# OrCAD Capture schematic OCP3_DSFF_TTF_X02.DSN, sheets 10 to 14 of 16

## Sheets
10 PAGE11 - NCSI Isolation: size Custom
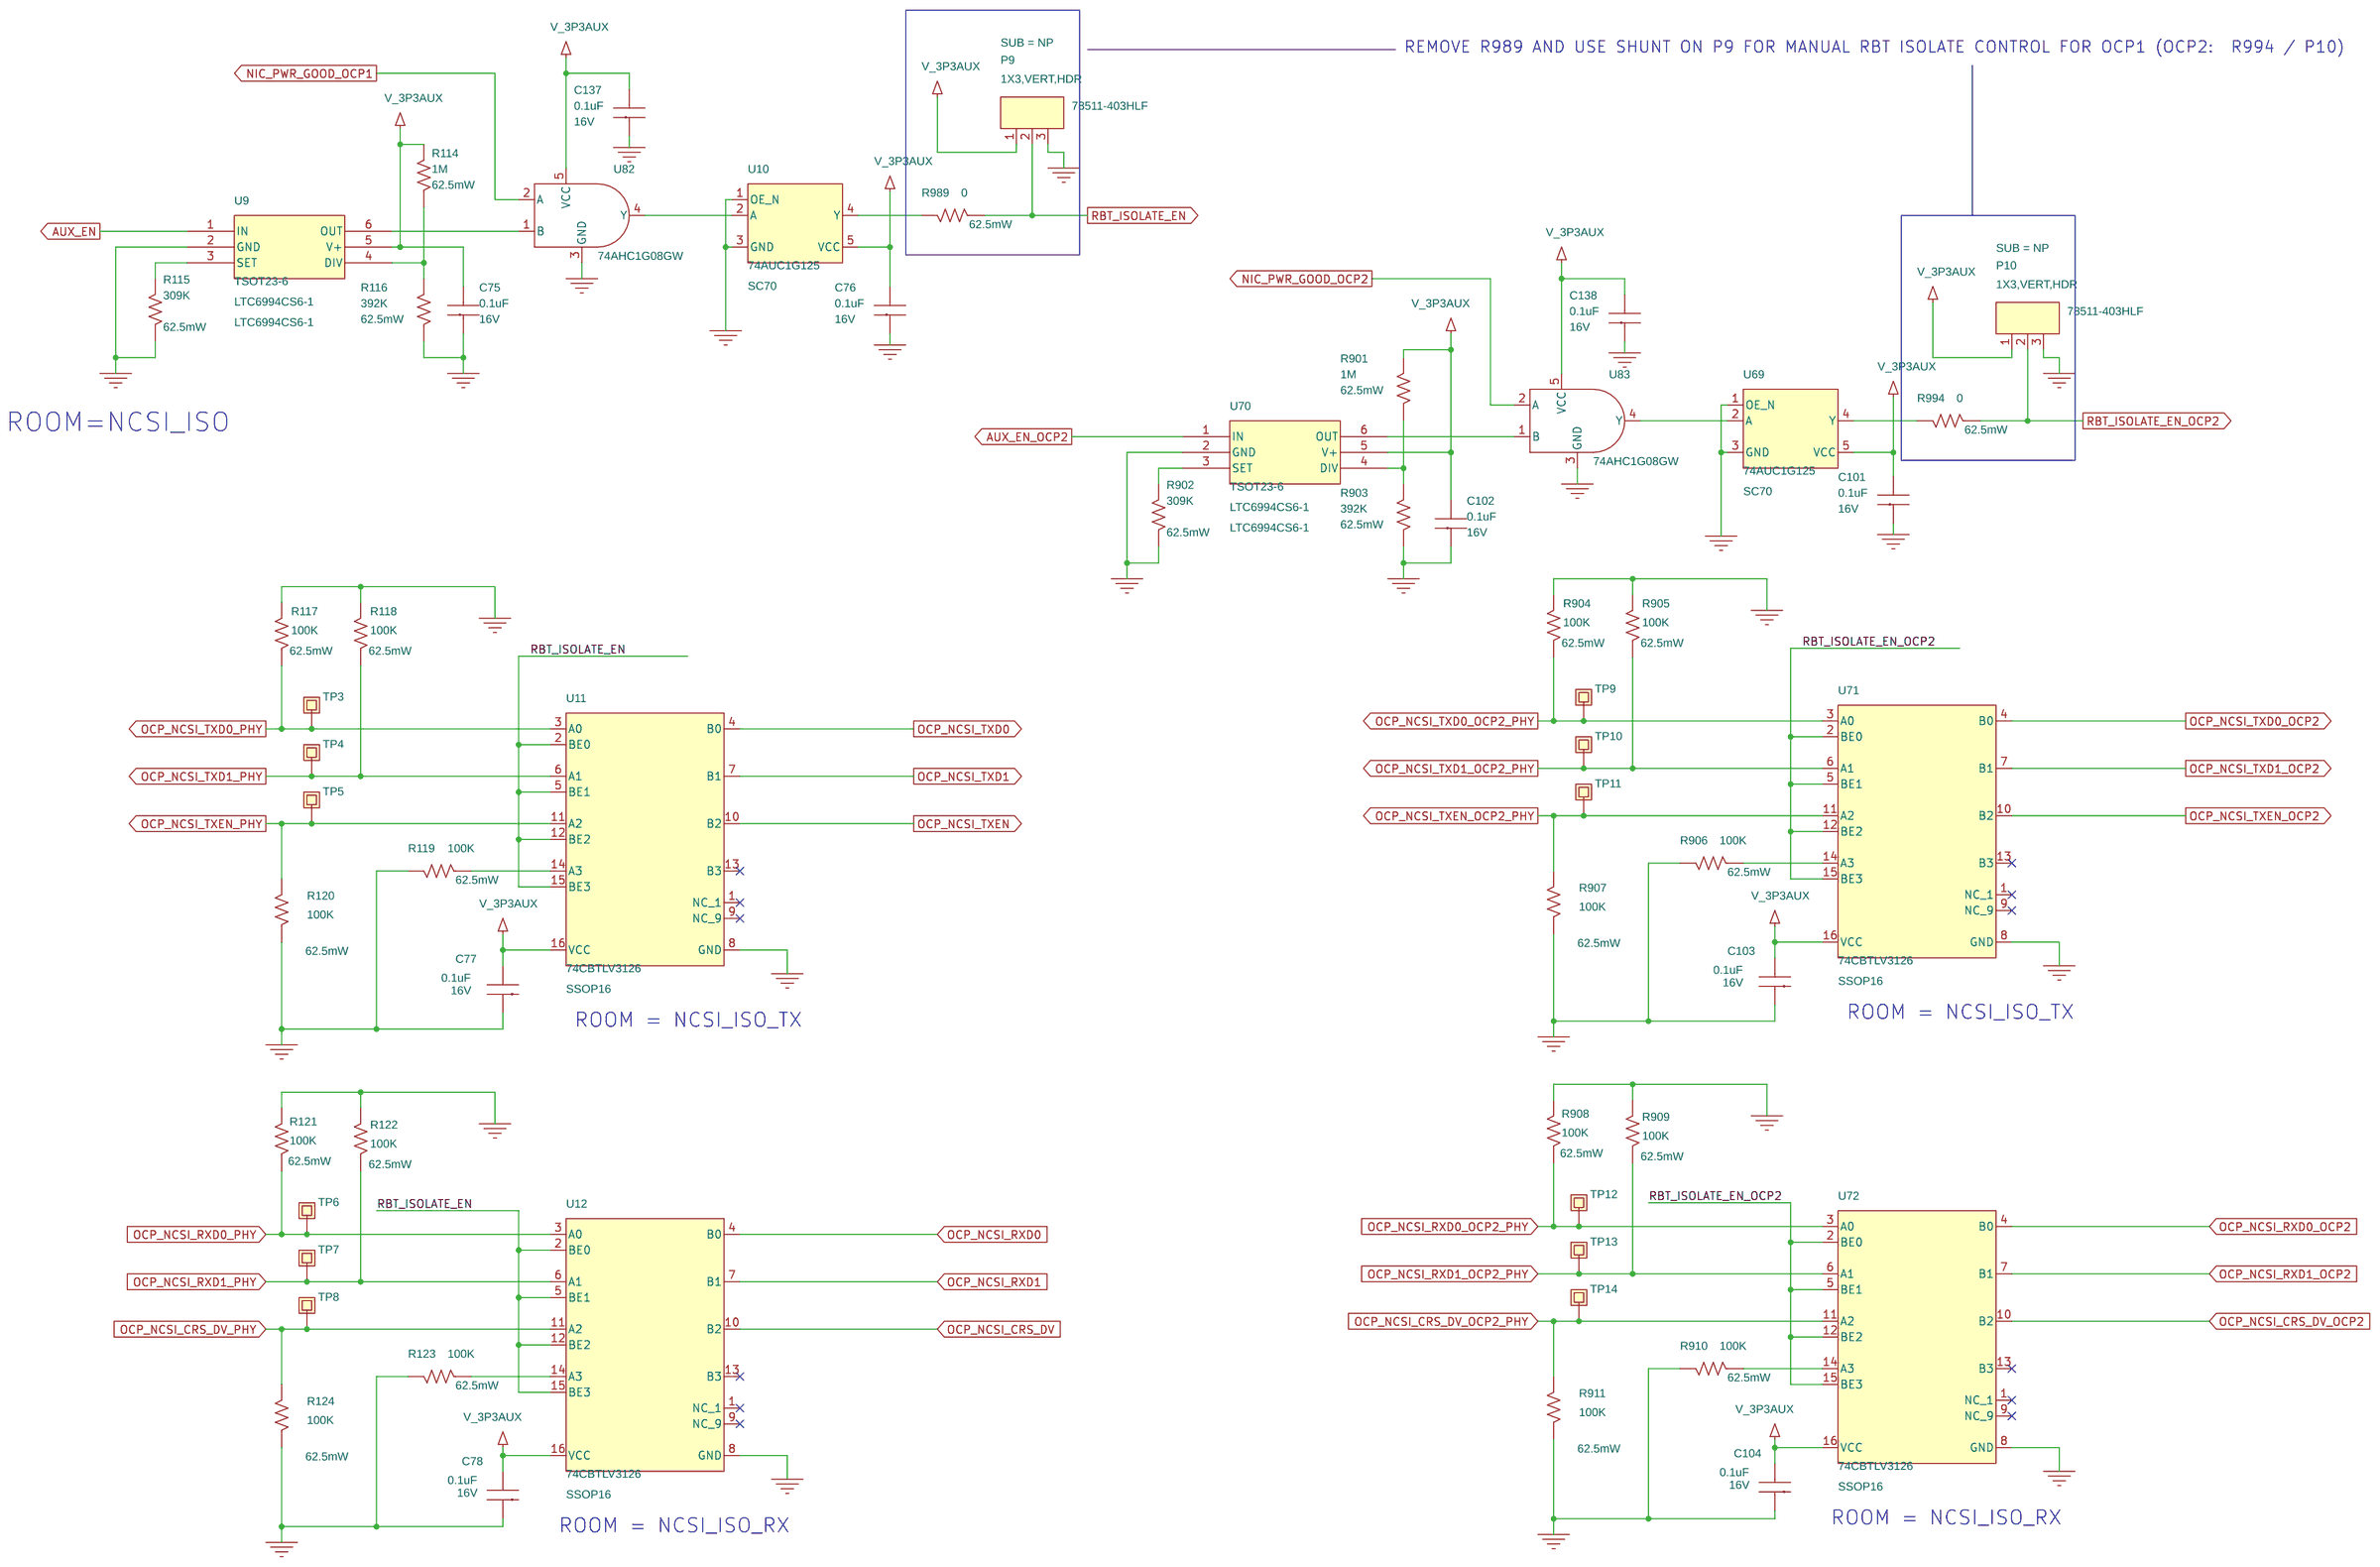
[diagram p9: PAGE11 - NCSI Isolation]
11 PAGE12 - NCSI PHY and RJ45: size Custom
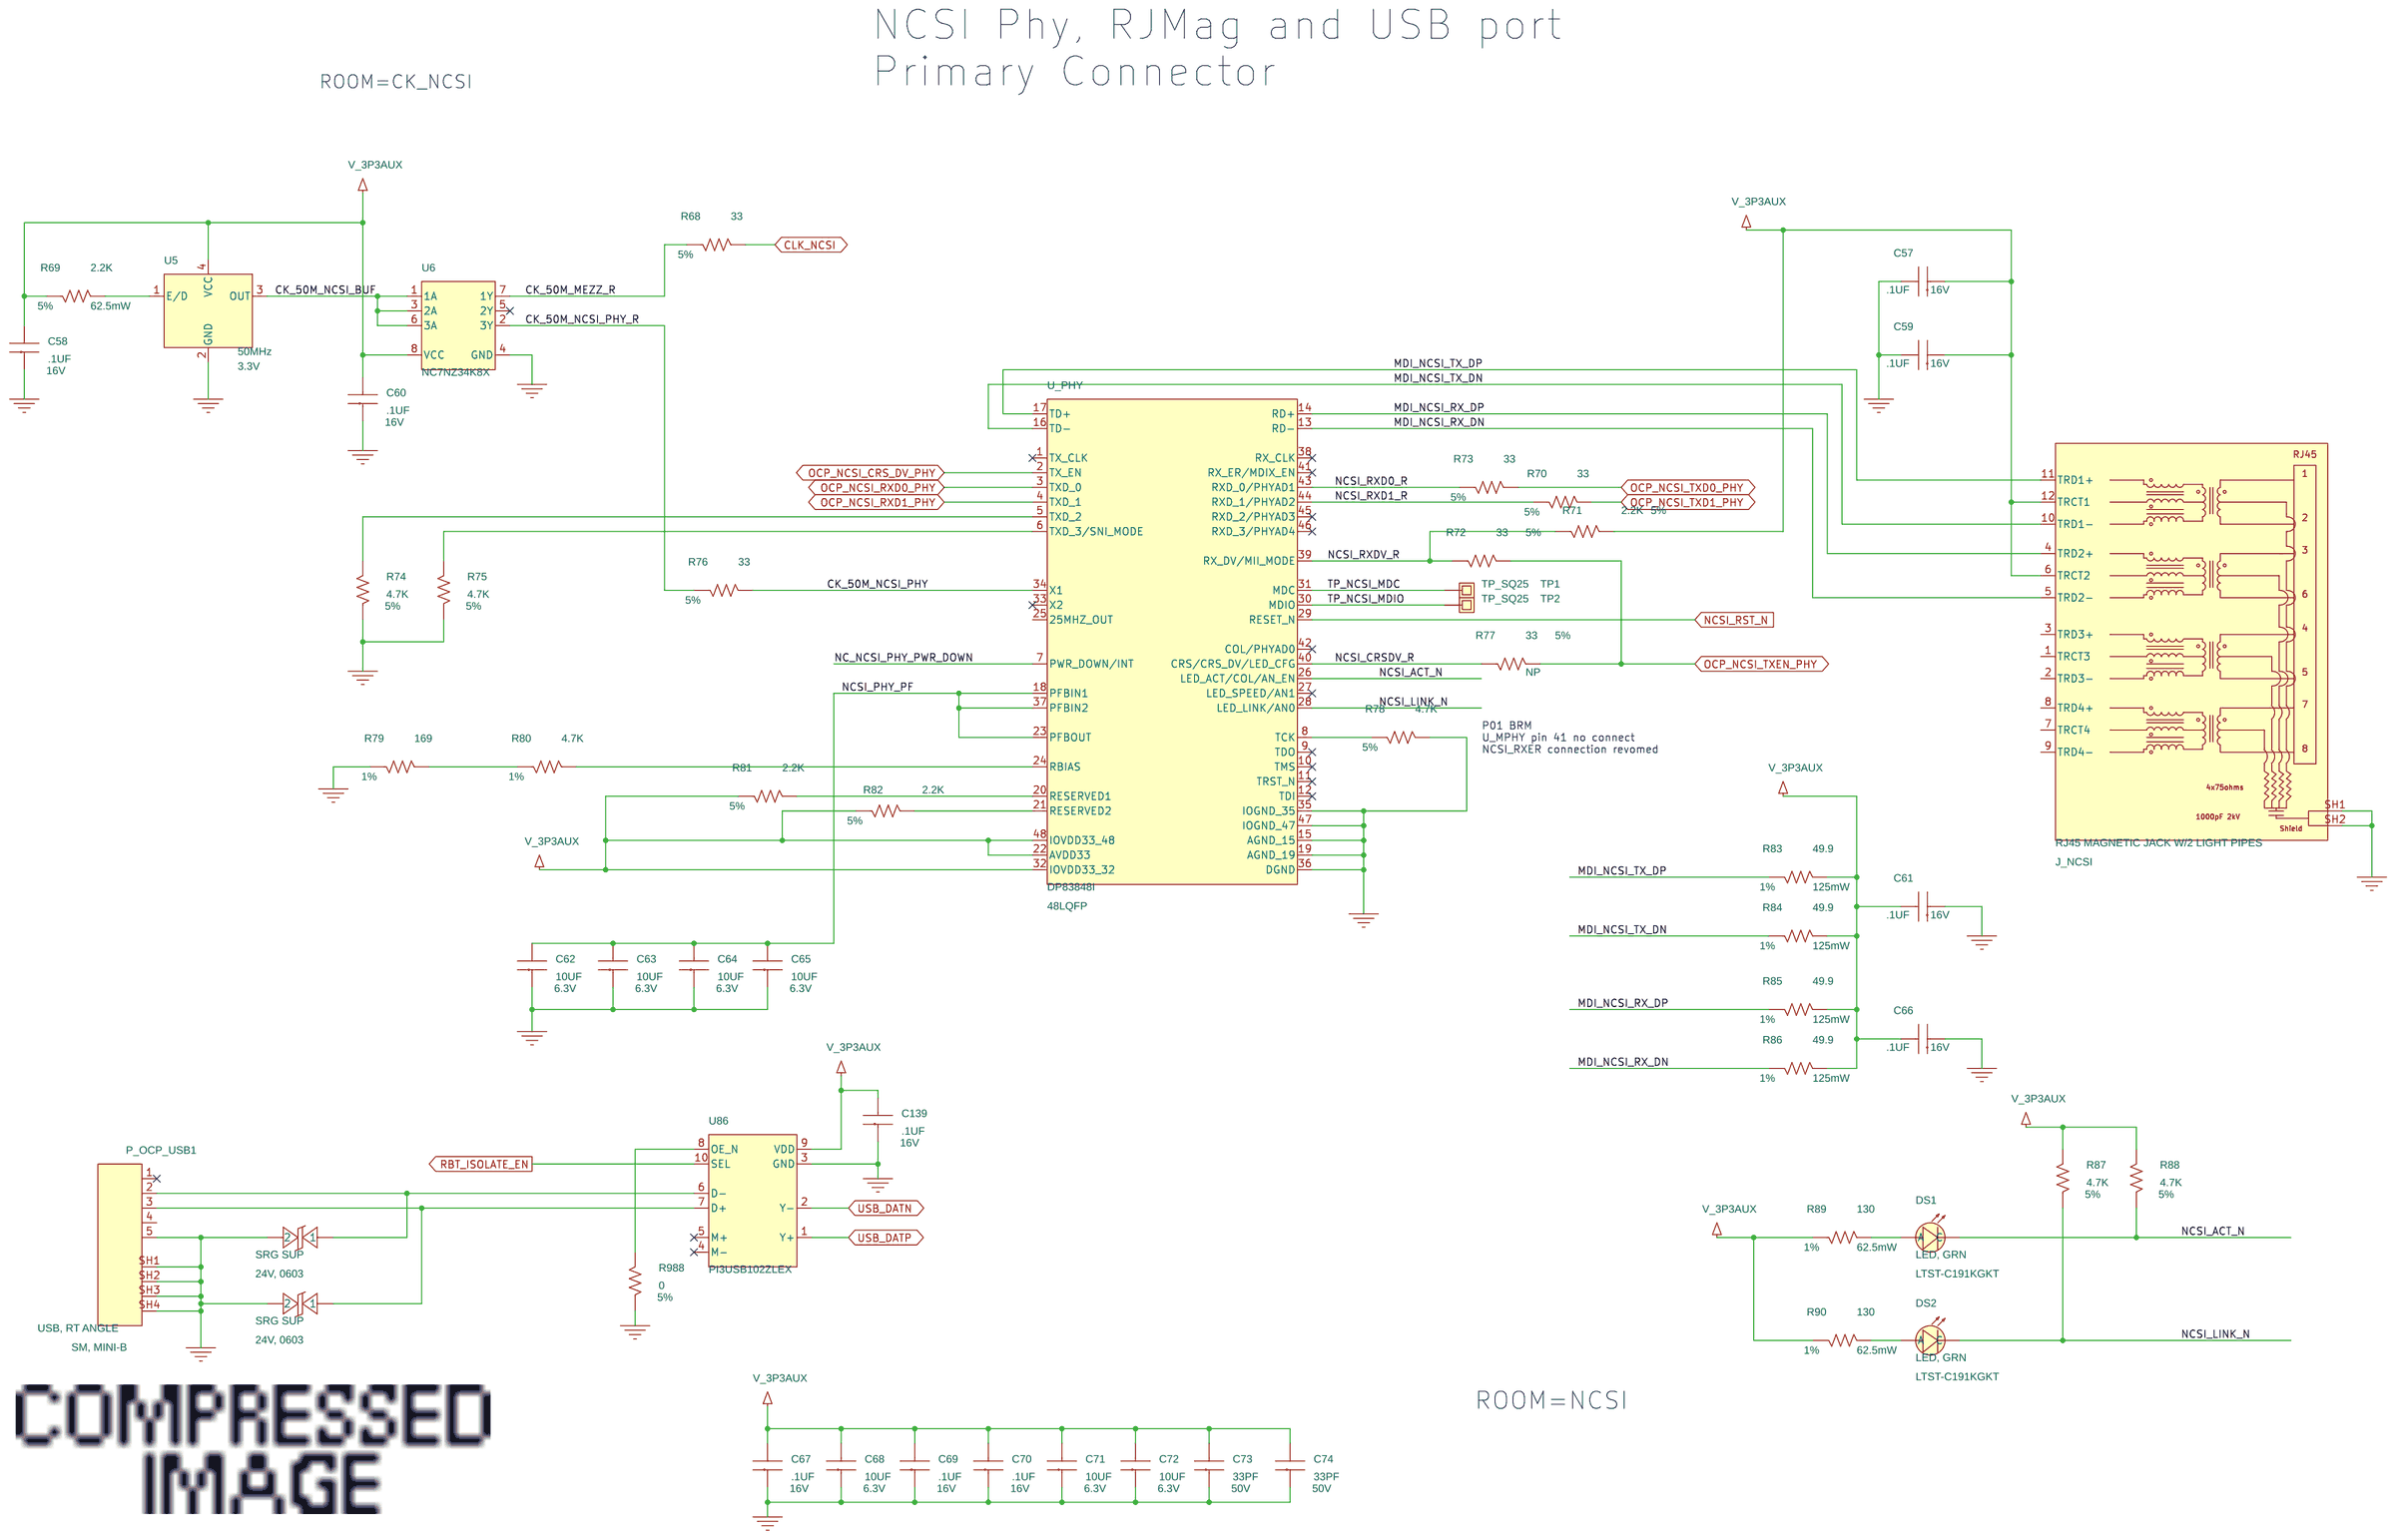
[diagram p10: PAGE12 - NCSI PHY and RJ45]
12 PAGE13 - NCSI PHY and RJ45 OCP2: size Custom
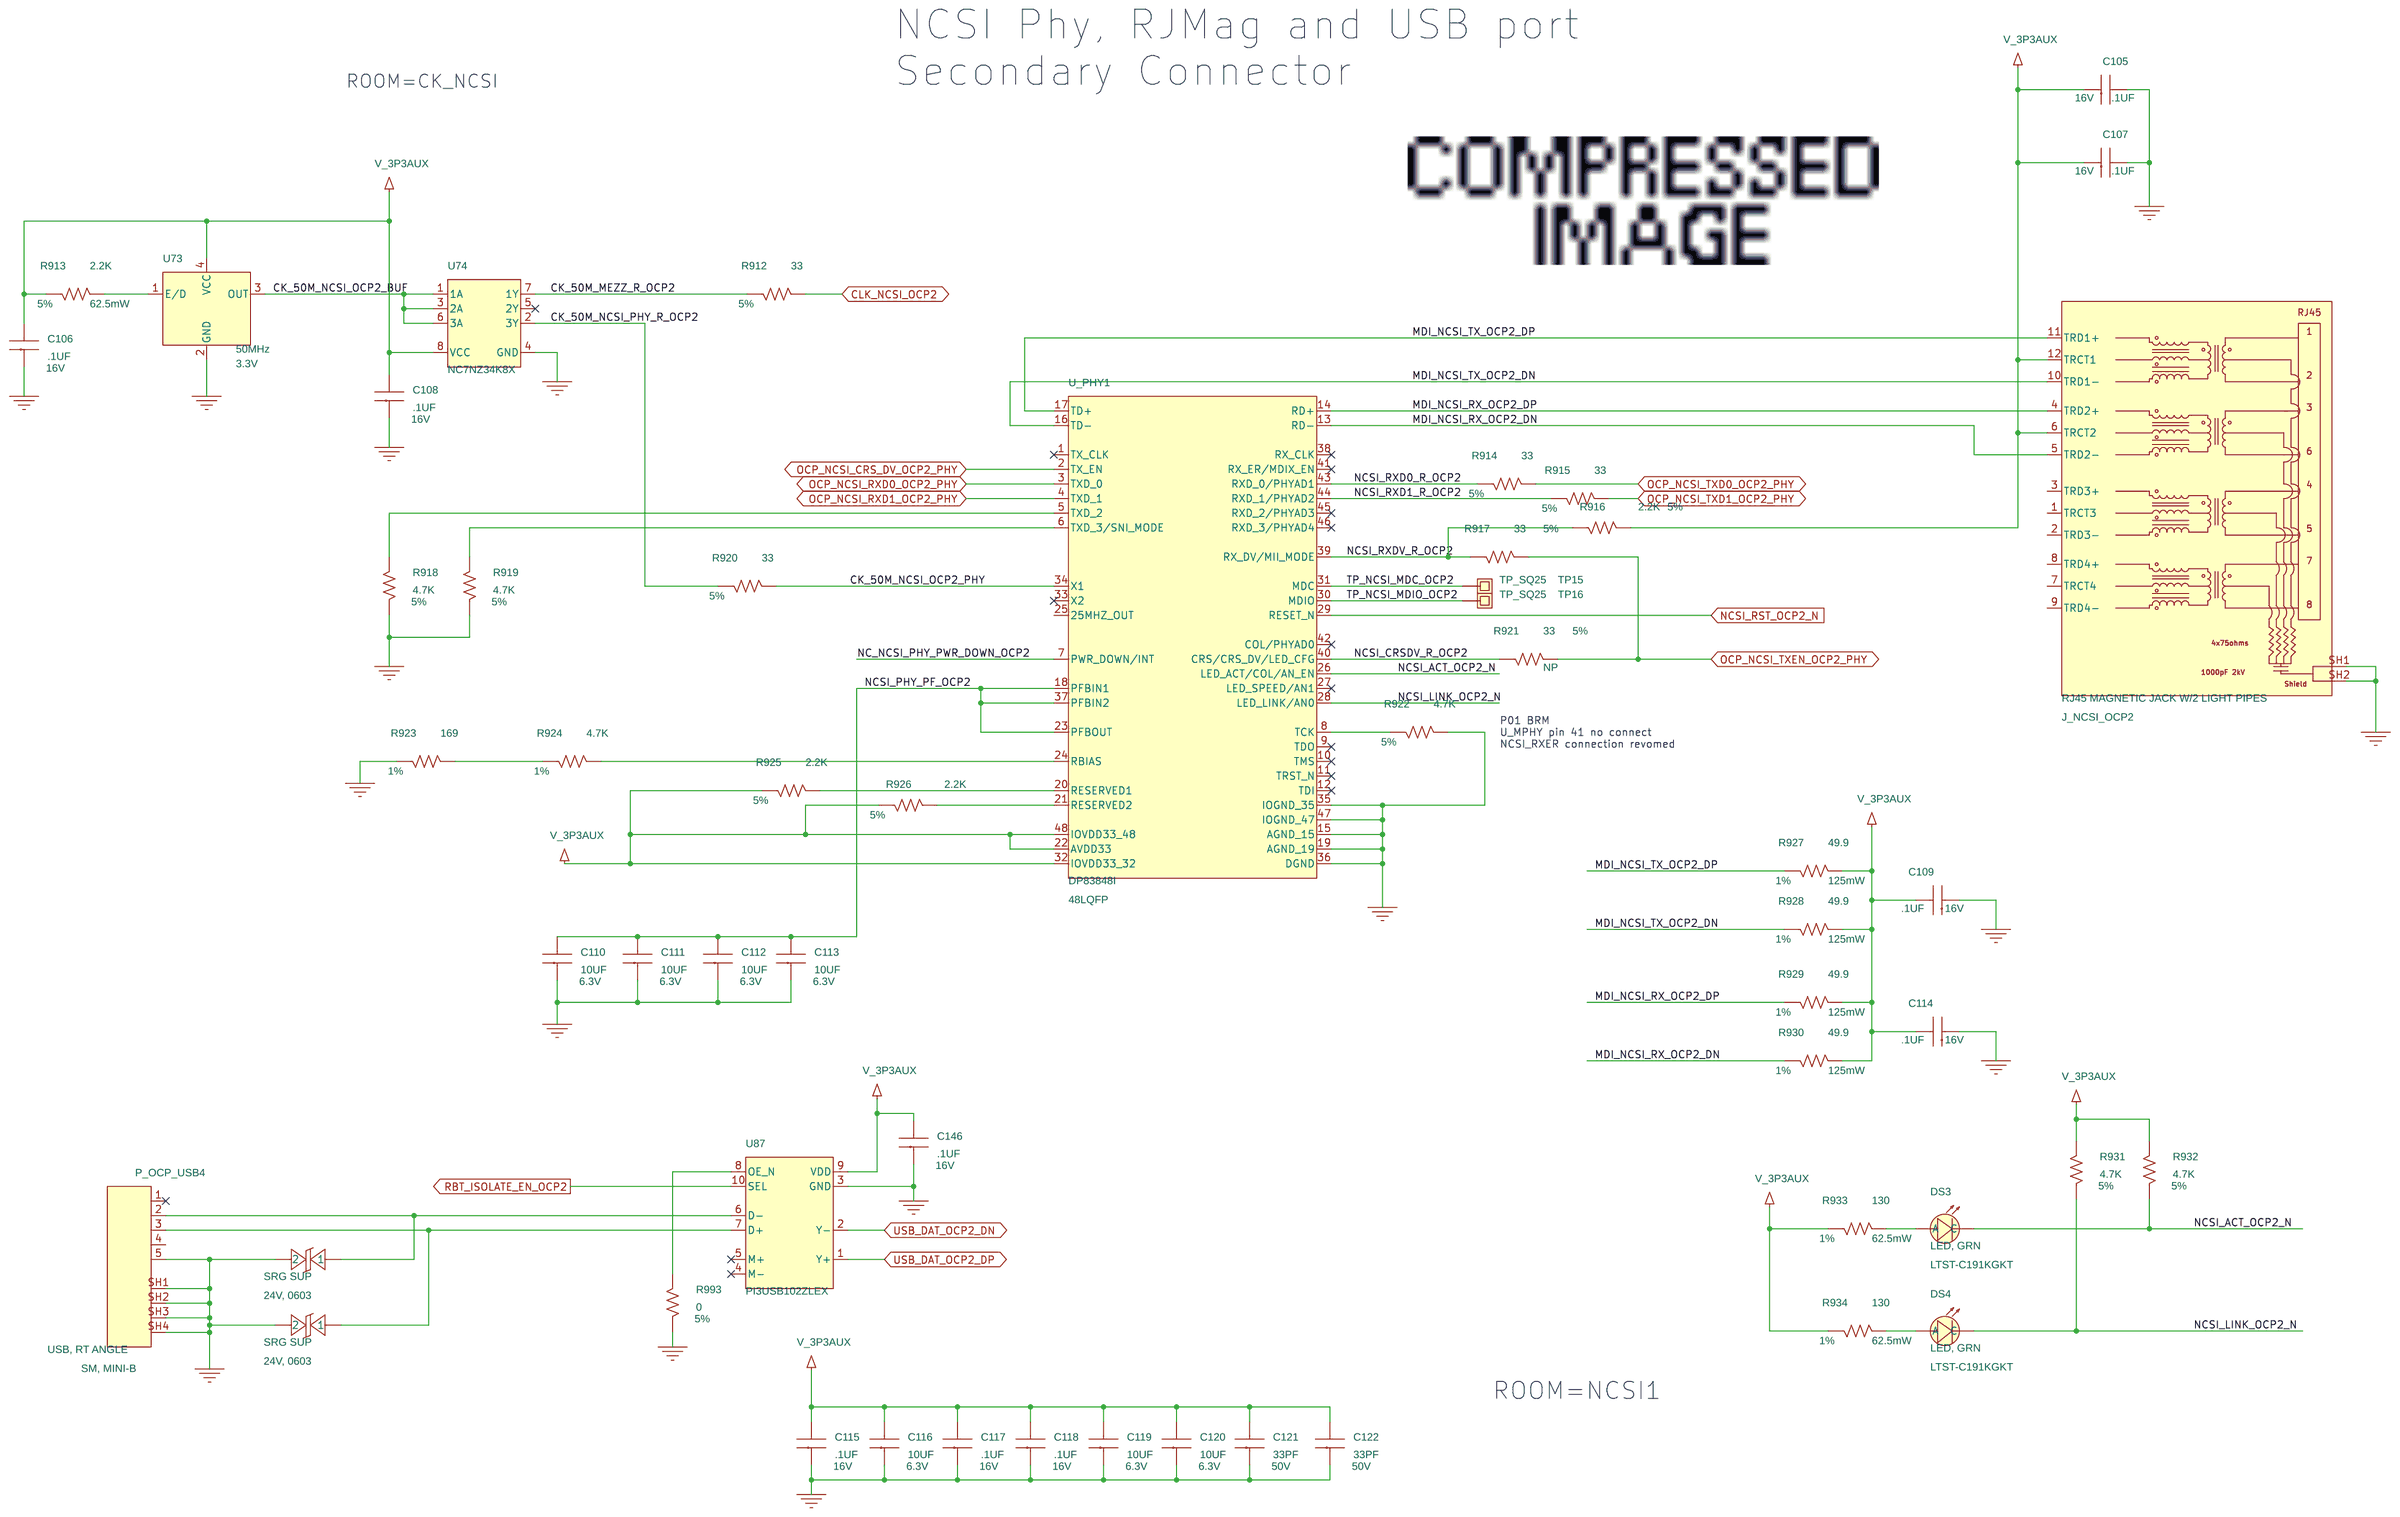
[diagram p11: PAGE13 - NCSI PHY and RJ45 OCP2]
13 PAGE14 - Clock Buf, PWR Conn: size Custom
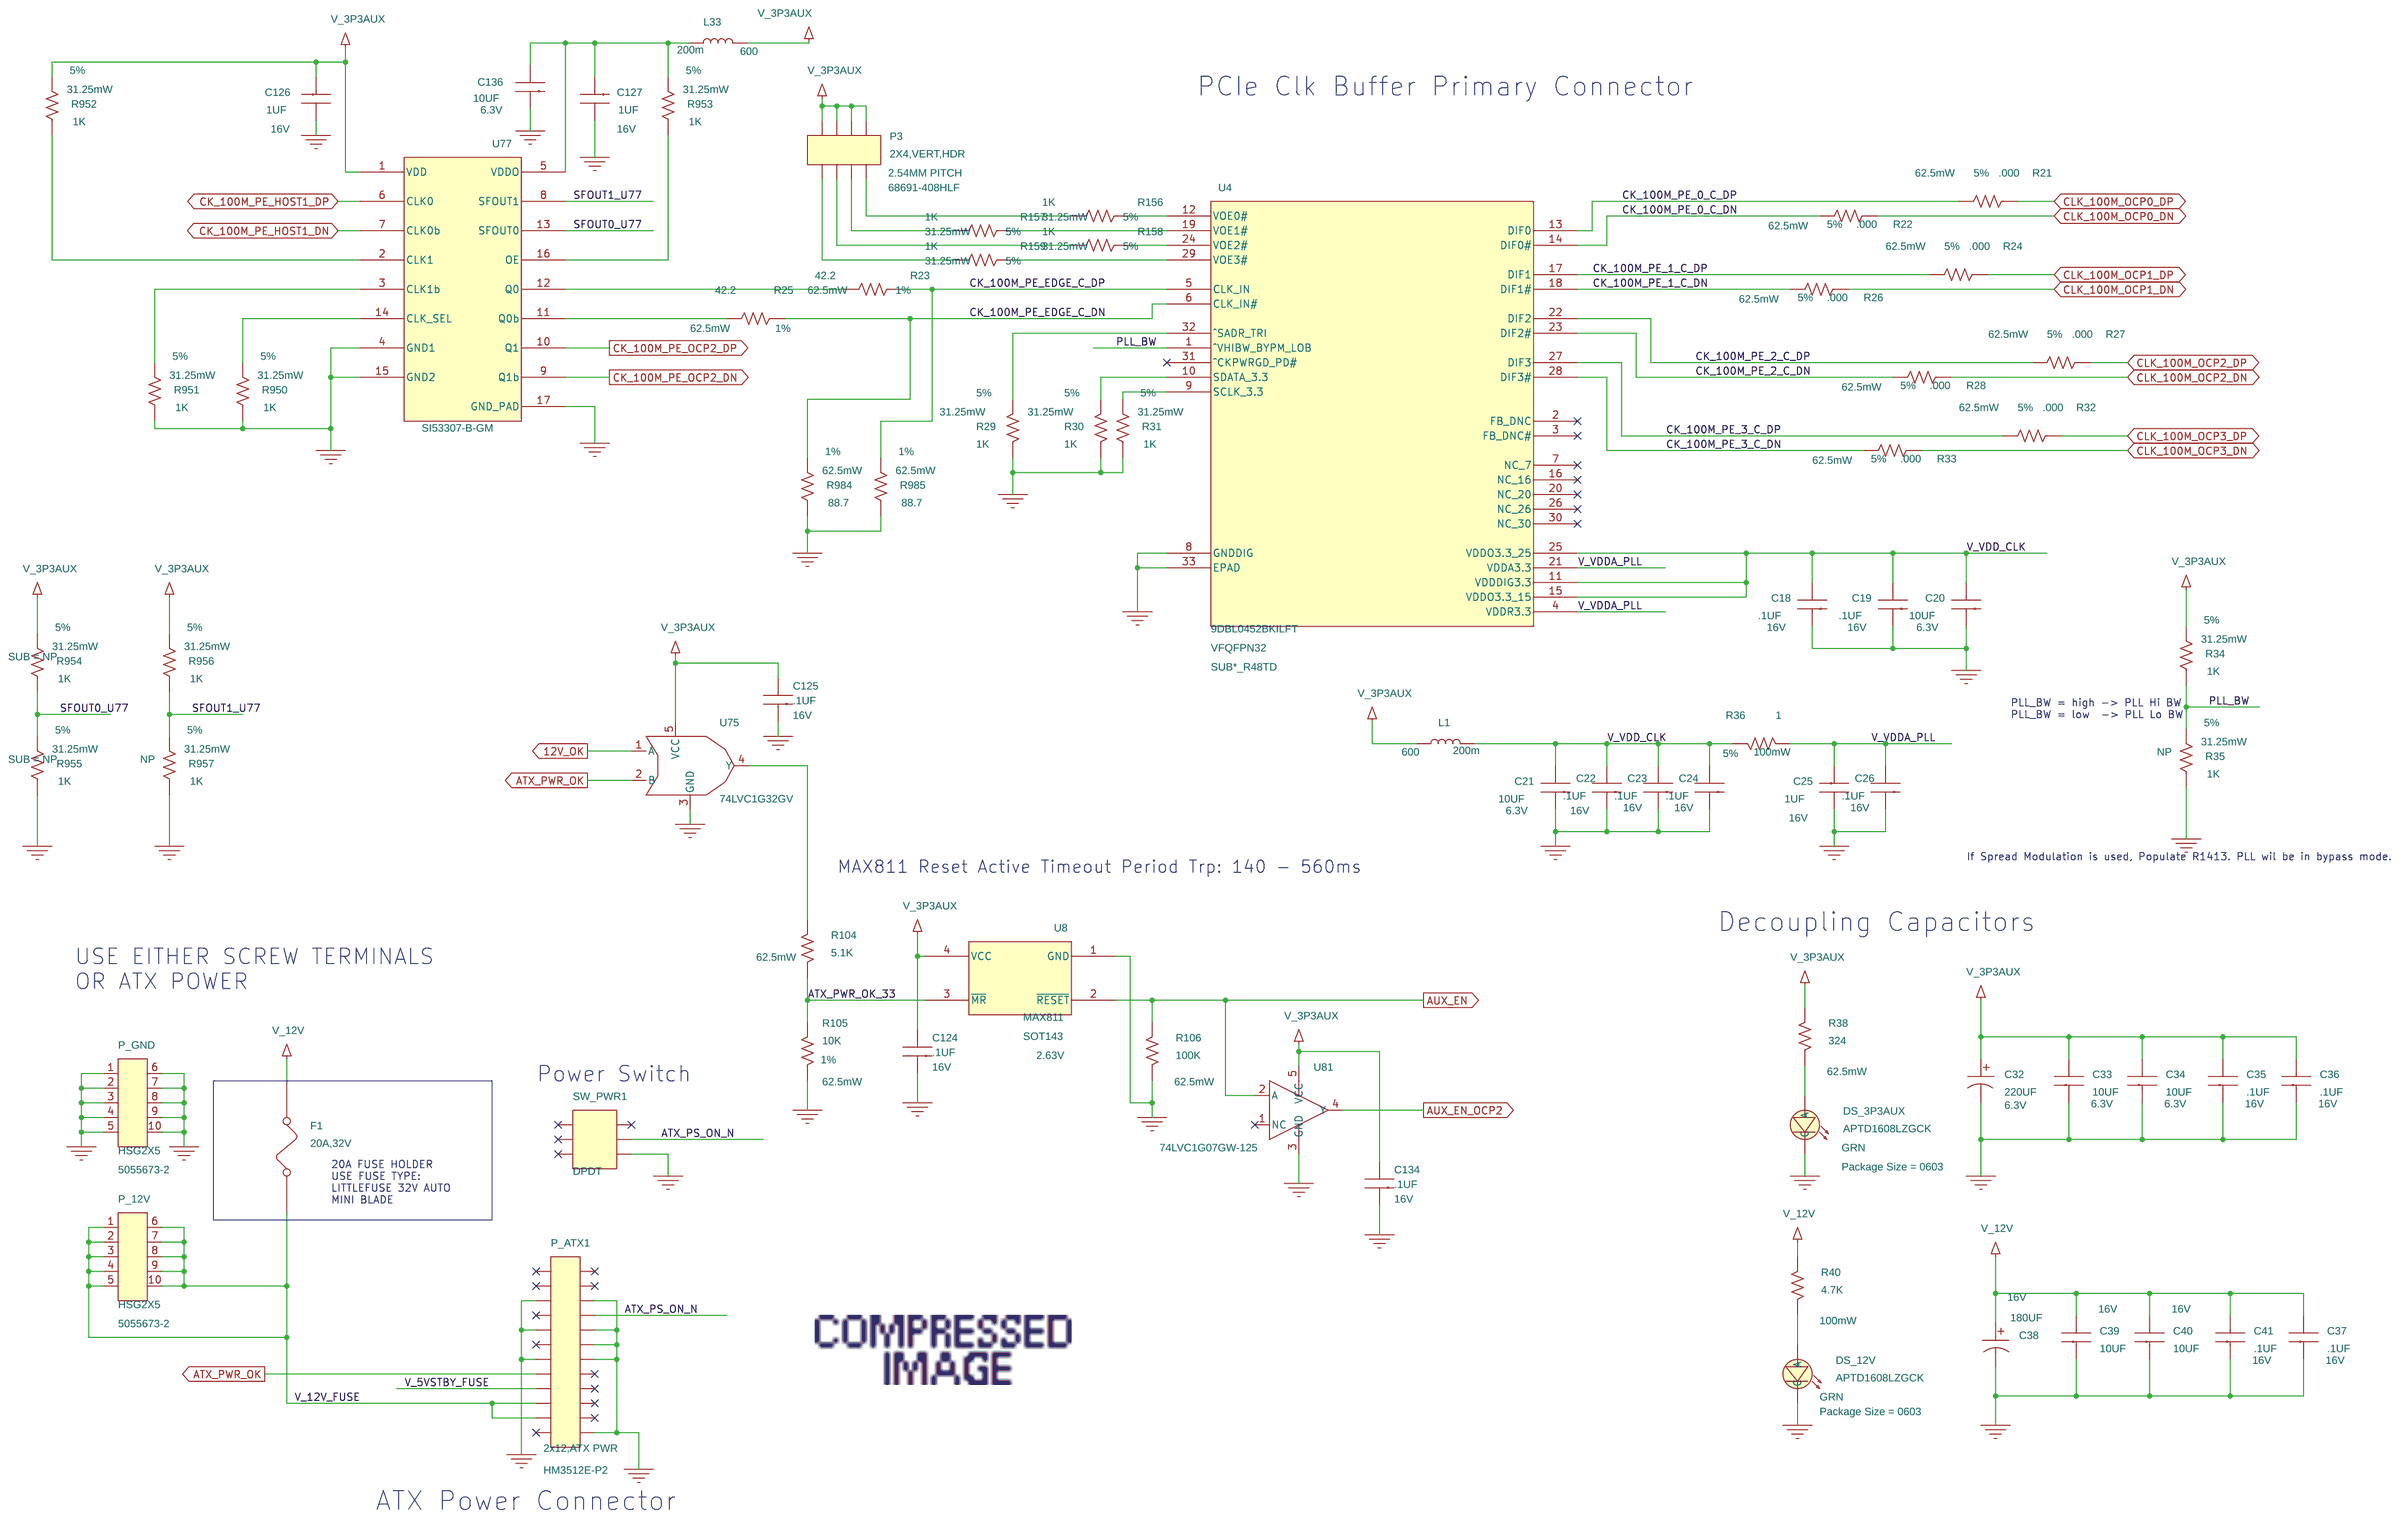
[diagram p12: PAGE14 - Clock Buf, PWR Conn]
14 PAGE15 - Secondary Clock Buf: size Custom
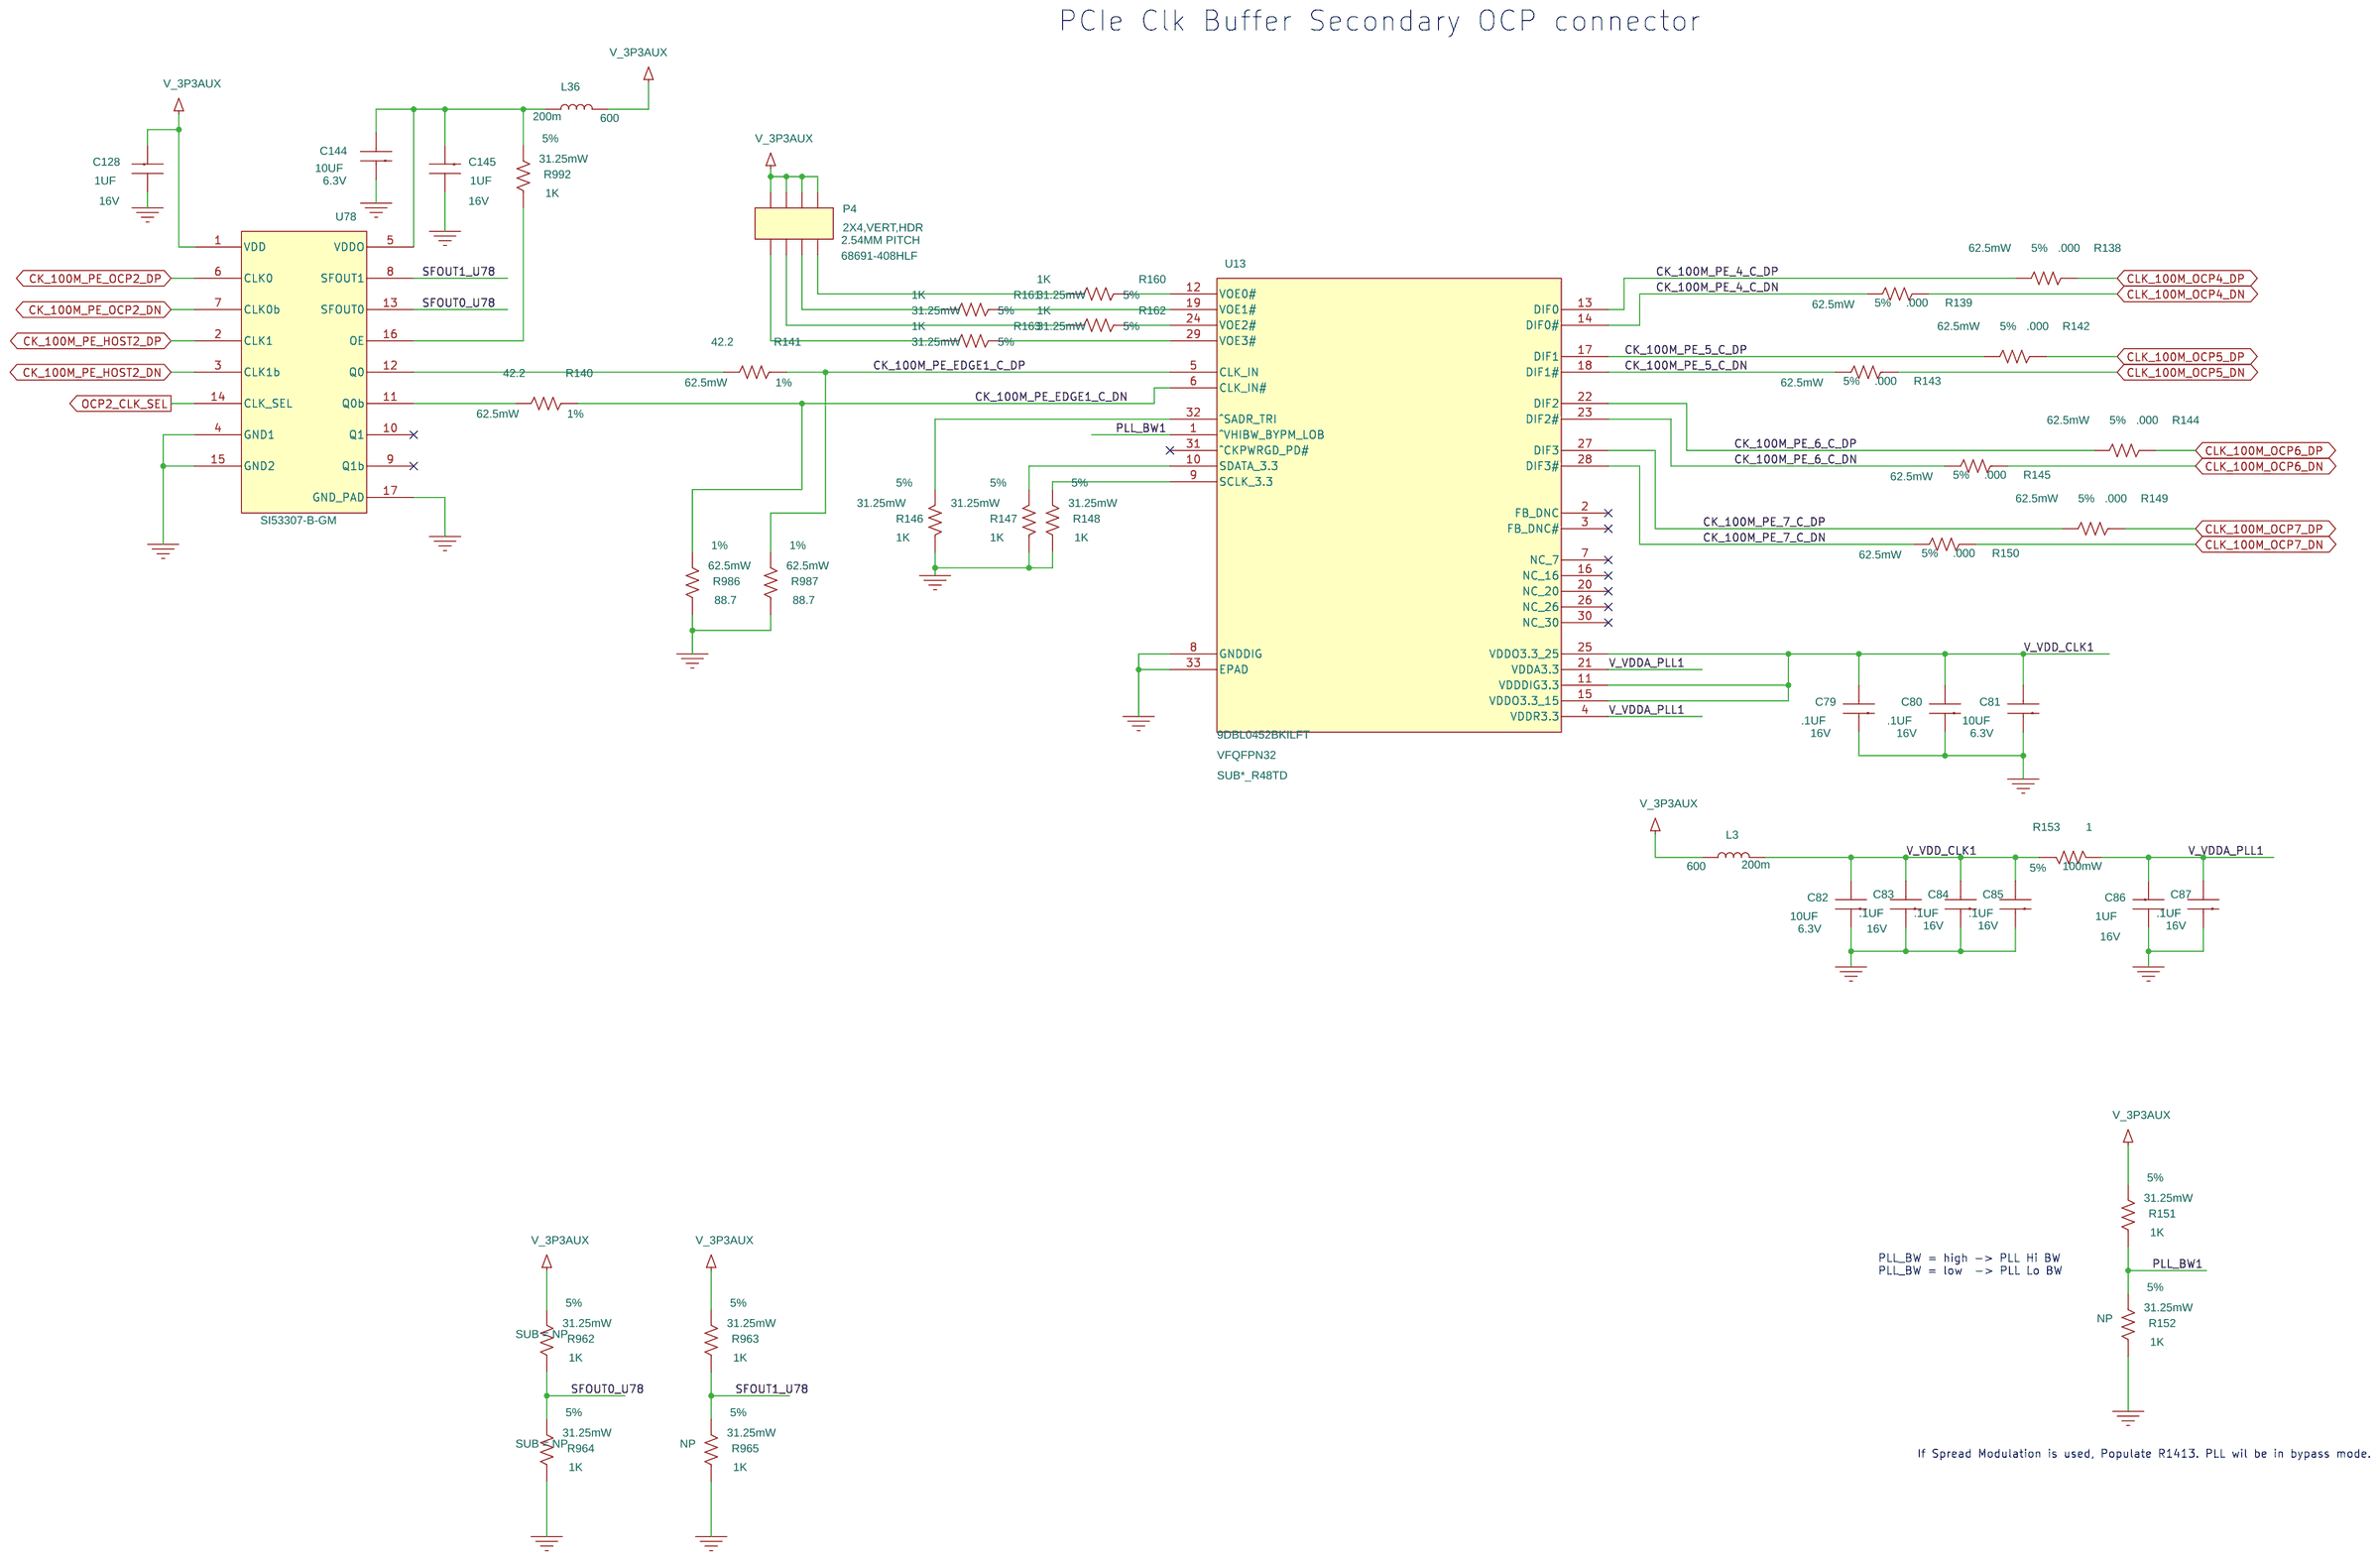
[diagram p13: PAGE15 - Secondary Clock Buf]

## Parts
sheet PAGE11 - NCSI Isolation
C75  0.1uF  [C0402]
C76  0.1uF  [C0402]
C77  0.1uF  [C0402]
C78  0.1uF  [C0402]
C101  0.1uF  [C0402]
C102  0.1uF  [C0402]
C103  0.1uF  [C0402]
C104  0.1uF  [C0402]
C137  0.1uF  [C0402]
C138  0.1uF  [C0402]
P9  1X3,VERT,HDR  [BERG1X3]
P10  1X3,VERT,HDR  [BERG1X3]
R114  1M  [R0402]
R115  309K  [R0402]
R116  392K  [R0402]
R117  100K  [R0402]
R118  100K  [R0402]
R119  100K  [R0402]
R120  100K  [R0402]
R121  100K  [R0402]
R122  100K  [R0402]
R123  100K  [R0402]
R124  100K  [R0402]
R901  1M  [R0402]
R902  309K  [R0402]
R903  392K  [R0402]
R904  100K  [R0402]
R905  100K  [R0402]
R906  100K  [R0402]
R907  100K  [R0402]
R908  100K  [R0402]
R909  100K  [R0402]
R910  100K  [R0402]
R911  100K  [R0402]
R989  0  [R0402]
R994  0  [R0402]
TP3  SM TEST PAD,24 MIL ROUND  [TP_RD24]
TP4  SM TEST PAD,24 MIL ROUND  [TP_RD24]
TP5  SM TEST PAD,24 MIL ROUND  [TP_RD24]
TP6  SM TEST PAD,24 MIL ROUND  [TP_RD24]
TP7  SM TEST PAD,24 MIL ROUND  [TP_RD24]
TP8  SM TEST PAD,24 MIL ROUND  [TP_RD24]
TP9  SM TEST PAD,24 MIL ROUND  [TP_RD24]
TP10  SM TEST PAD,24 MIL ROUND  [TP_RD24]
TP11  SM TEST PAD,24 MIL ROUND  [TP_RD24]
TP12  SM TEST PAD,24 MIL ROUND  [TP_RD24]
TP13  SM TEST PAD,24 MIL ROUND  [TP_RD24]
TP14  SM TEST PAD,24 MIL ROUND  [TP_RD24]
U9  LTC6994CS6-1  [SOT95P280X100_6N]
U10  74AUC1G125  [SOT65P210X110_5N]
U11  74CBTLV3126  [SOP63P600X175_16N]
U12  74CBTLV3126  [SOP63P600X175_16N]
U69  74AUC1G125  [SOT65P210X110_5N]
U70  LTC6994CS6-1  [SOT95P280X100_6N]
U71  74CBTLV3126  [SOP63P600X175_16N]
U72  74CBTLV3126  [SOP63P600X175_16N]
U82  74AHC1G08GW  [SOT65P210X110_5L]
U83  74AHC1G08GW  [SOT65P210X110_5L]
sheet PAGE12 - NCSI PHY and RJ45
C57  .1UF  [C0402]
C58  .1UF  [C0402]
C59  .1UF  [C0402]
C60  .1UF  [C0402]
C61  .1UF  [C0402]
C62  10UF  [C0603]
C63  10UF  [C0603]
C64  10UF  [C0603]
C65  10UF  [C0603]
C66  .1UF  [C0402]
C67  .1UF  [C0402]
C68  10UF  [C0603]
C69  .1UF  [C0402]
C70  .1UF  [C0402]
C71  10UF  [C0603]
C72  10UF  [C0603]
C73  33PF  [C0402]
C74  33PF  [C0402]
C139  .1UF  [C0402]
D5  g_diode_bi_tvs  [FUSE_ESD_0603]
D6  g_diode_bi_tvs  [FUSE_ESD_0603]
DS1  g_led_a1_c2  [LEDC1608X65N]
DS2  g_led_a1_c2  [LEDC1608X65N]
J_NCSI  c12raf_rj45magth_2ltp_td  [C12RAF_RJ45MAGTH_2LTP_TD]
P_OCP_USB1  g_c5raf_musb_p8sm_4sh_2peg  [C5RAF_MUSB_P8SM_4SH_2PEG]
R68  33  [R0402]
R69  2.2K  [R0402]
R70  33  [R0402]
R71  2.2K  [R0402]
R72  33  [R0402]
R73  33  [R0402]
R74  4.7K  [R0402]
R75  4.7K  [R0402]
R76  33  [R0402]
R77  33  [R0402]
R78  4.7K  [R0402]
R79  169  [R0402]
R80  4.7K  [R0402]
R81  2.2K  [R0402]
R82  2.2K  [R0402]
R83  49.9  [R0805]
R84  49.9  [R0805]
R85  49.9  [R0805]
R86  49.9  [R0805]
R87  4.7K  [R0402]
R88  4.7K  [R0402]
R89  130  [R0402]
R90  130  [R0402]
R988  0  [R0402]
TP1  g_tp  [TP_SQ25]
TP2  g_tp  [TP_SQ25]
U5  g_osc_4p  [OSC508P500X730X180_4N]
U6  nc7nz34  [TSSOP50P310X100_8N]
U86  PI3USB102ZLEX  [QFN40P130X160X80-10N]
U_PHY  dp83848i  [TSQFP50P900X900X120_48N]
sheet PAGE13 - NCSI PHY and RJ45 OCP2
C105  .1UF  [C0402]
C106  .1UF  [C0402]
C107  .1UF  [C0402]
C108  .1UF  [C0402]
C109  .1UF  [C0402]
C110  10UF  [C0603]
C111  10UF  [C0603]
C112  10UF  [C0603]
C113  10UF  [C0603]
C114  .1UF  [C0402]
C115  .1UF  [C0402]
C116  10UF  [C0603]
C117  .1UF  [C0402]
C118  .1UF  [C0402]
C119  10UF  [C0603]
C120  10UF  [C0603]
C121  33PF  [C0402]
C122  33PF  [C0402]
C146  .1UF  [C0402]
D11  g_diode_bi_tvs  [FUSE_ESD_0603]
D12  g_diode_bi_tvs  [FUSE_ESD_0603]
DS3  g_led_a1_c2  [LEDC1608X65N]
DS4  g_led_a1_c2  [LEDC1608X65N]
J_NCSI_OCP2  c12raf_rj45magth_2ltp_td  [C12RAF_RJ45MAGTH_2LTP_TD]
P_OCP_USB4  g_c5raf_musb_p8sm_4sh_2peg  [C5RAF_MUSB_P8SM_4SH_2PEG]
R912  33  [R0402]
R913  2.2K  [R0402]
R914  33  [R0402]
R915  33  [R0402]
R916  2.2K  [R0402]
R917  33  [R0402]
R918  4.7K  [R0402]
R919  4.7K  [R0402]
R920  33  [R0402]
R921  33  [R0402]
R922  4.7K  [R0402]
R923  169  [R0402]
R924  4.7K  [R0402]
R925  2.2K  [R0402]
R926  2.2K  [R0402]
R927  49.9  [R0805]
R928  49.9  [R0805]
R929  49.9  [R0805]
R930  49.9  [R0805]
R931  4.7K  [R0402]
R932  4.7K  [R0402]
R933  130  [R0402]
R934  130  [R0402]
R993  0  [R0402]
TP15  g_tp  [TP_SQ25]
TP16  g_tp  [TP_SQ25]
U73  g_osc_4p  [OSC508P500X730X180_4N]
U74  nc7nz34  [TSSOP50P310X100_8N]
U87  PI3USB102ZLEX  [QFN40P130X160X80-10N]
U_PHY1  dp83848i  [TSQFP50P900X900X120_48N]
sheet PAGE14 - Clock Buf, PWR Conn
C18  .1UF  [C0402]
C19  .1UF  [C0402]
C20  10UF  [C0603]
C21  10UF  [C0603]
C22  .1UF  [C0402]
C23  .1UF  [C0402]
C24  .1UF  [C0402]
C25  1UF  [C0603]
C26  .1UF  [C0402]
C32  220UF  [CAPAE680X600N]
C33  10UF  [C0603]
C34  10UF  [C0603]
C35  .1UF  [C0402]
C36  .1UF  [C0402]
C37  .1UF  [C0402]
C38  180UF  [CAPAE680X600N]
C39  10UF  [C1206]
C40  10UF  [C1206]
C41  .1UF  [C0402]
C124  .1UF  [C0402]
C125  .1UF  [C0402]
C126  1UF  [C0603]
C127  1UF  [C0603]
C134  .1UF  [C0402]
C136  10UF  [C0603]
DS_3P3AUX  APTD1608LZGCK  [LEDC1608X95N]
DS_12V  APTD1608LZGCK  [LEDC1608X95N]
F1  20A,32V  [LITTELFUSE_01530008Z]
L1  600  [FR0603]
L33  600  [FR0603]
P3  2X4,VERT,HDR  [BERG2X4]
P_12V  HSG2X5  [TB10_PWRDIST_632_500X400]
P_ATX1  2x12,ATX PWR  [CON_HDR_2X12_ST_TH_PWR]
P_GND  HSG2X5  [TB10_PWRDIST_632_500X400]
R21  .000  [R0402]
R22  .000  [R0402]
R23  42.2  [R0402]
R24  .000  [R0402]
R25  42.2  [R0402]
R26  .000  [R0402]
R27  .000  [R0402]
R28  .000  [R0402]
R29  1K  [R0402]
R30  1K  [R0402]
R31  1K  [R0402]
R32  .000  [R0402]
R33  .000  [R0402]
R34  1K  [R0402]
R35  1K  [R0402]
R36  1  [R0603]
R38  324  [R0402]
R40  4.7K  [R0603]
R104  5.1K  [R0402]
R105  10K  [R0402]
R106  100K  [R0402]
R156  1K  [R0402]
R157  1K  [R0402]
R158  1K  [R0402]
R159  1K  [R0402]
R950  1K  [R0402]
R951  1K  [R0402]
R952  1K  [R0402]
R953  1K  [R0402]
R954  1K  [R0402]
R955  1K  [R0402]
R956  1K  [R0402]
R957  1K  [R0402]
R984  88.7  [R0402]
R985  88.7  [R0402]
SW_PWR1  DPDT  [SW6ST_2P00TH_2MH]
U4  9dbl04  [QFN50P500X500X100_33N3P3]
U8  MAX811  [SOT192P237X122_4N]
U75  74LVC1G32GV  [SOT95P280X145_5N]
U77  SI53307-B-GM  [QFN50P300X300X90-17]
U81  74LVC1G07GW-125  [SOT65P210X110_5N]
sheet PAGE15 - Secondary Clock Buf
C79  .1UF  [C0402]
C80  .1UF  [C0402]
C81  10UF  [C0603]
C82  10UF  [C0603]
C83  .1UF  [C0402]
C84  .1UF  [C0402]
C85  .1UF  [C0402]
C86  1UF  [C0603]
C87  .1UF  [C0402]
C128  1UF  [C0603]
C144  10UF  [C0603]
C145  1UF  [C0603]
L3  600  [FR0603]
L36  600  [FR0603]
P4  2X4,VERT,HDR  [BERG2X4]
R138  .000  [R0402]
R139  .000  [R0402]
R140  42.2  [R0402]
R141  42.2  [R0402]
R142  .000  [R0402]
R143  .000  [R0402]
R144  .000  [R0402]
R145  .000  [R0402]
R146  1K  [R0402]
R147  1K  [R0402]
R148  1K  [R0402]
R149  .000  [R0402]
R150  .000  [R0402]
R151  1K  [R0402]
R152  1K  [R0402]
R153  1  [R0603]
R160  1K  [R0402]
R161  1K  [R0402]
R162  1K  [R0402]
R163  1K  [R0402]
R962  1K  [R0402]
R963  1K  [R0402]
R964  1K  [R0402]
R965  1K  [R0402]
R986  88.7  [R0402]
R987  88.7  [R0402]
R992  1K  [R0402]
U13  9dbl04  [QFN50P500X500X100_33N3P3]
U78  SI53307-B-GM  [QFN50P300X300X90-17]

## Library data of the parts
C75 C76 C101 C102 C137 C138 = cap: CAP,0.1UF,10%,16V,X7R,0402; ALT_SYMBOLS: (SMX0402B); CLASS: DISCRETE; DEVICE: 090729120334; DPN: P8155; Dielectric Type: X7R; Lead Free: Yes; Lifecycle Phase: A Revision; Manufacturer: KEMET ELECTRONICS; Manufacturer PN: C0402C104K4RAC; Package Height: 24 MIL; Package Size: 0402; Package Type: SMD; Part Number: P8155; ROOM: NCSI_ISO; Rev: A00-00; TOLERANCE: 10%; VOLTAGE: 16V
C77 C103 = cap: CAP,0.1UF,10%,16V,X7R,0402; ALT_SYMBOLS: (SMX0402B); CLASS: DISCRETE; DEVICE: 090729120334; DPN: P8155; Dielectric Type: X7R; Lead Free: Yes; Lifecycle Phase: A Revision; Manufacturer: KEMET ELECTRONICS; Manufacturer PN: C0402C104K4RAC; Package Height: 24 MIL; Package Size: 0402; Package Type: SMD; Part Number: P8155; ROOM: NCSI_ISO_TX; Rev: A00-00; TOLERANCE: 10%; VOLTAGE: 16V
C78 C104 = cap: CAP,0.1UF,10%,16V,X7R,0402; ALT_SYMBOLS: (SMX0402B); CLASS: DISCRETE; DEVICE: 090729120334; DPN: P8155; Dielectric Type: X7R; Lead Free: Yes; Lifecycle Phase: A Revision; Manufacturer: KEMET ELECTRONICS; Manufacturer PN: C0402C104K4RAC; Package Height: 24 MIL; Package Size: 0402; Package Type: SMD; Part Number: P8155; ROOM: NCSI_ISO_RX; Rev: A00-00; TOLERANCE: 10%; VOLTAGE: 16V
P9 P10 = g_1x3: CON,HDR,1X3,M,.1X.32,S,T,U,TH; Manufacturer: FCI; Manufacturer PN: 78511-403HLF; Package Height: 426 MIL; Part Number: NC997; SUB: NP
R114 R901 = res: RES,1MEG,1/16W,1%,THKFLM,0402; CLASS: DISCRETE; DPN: WG904; Lead Free: Yes; Lifecycle Phase: A Revision; Manufacturer: KOA; Manufacturer PN: RK73H1ETTP1004F; Material: Thick Film; Package Height: 16 MIL; Package Size: 0402; Package Type: SMD; Part Number: WG904; ROOM: NCSI_ISO; Rated Power: 62.5mW; Rev: A00-00; Tolerance: 1%
R115 R902 = res: RES,309K,1/16W,1%,THKFLM,0402; CLASS: DISCRETE; DPN: X15JT; Lead Free: Yes; Lifecycle Phase: X Revision; Manufacturer: KOA; Manufacturer PN: RK73H1ETTP3093F; Material: Thick Film; Package Height: 16 MIL; Package Size: 0402; Package Type: SMD; Part Number: X15JT; ROOM: NCSI_ISO; Rated Power: 62.5mW; Rev: X00-00; Tolerance: 1%
R116 R903 = res: RES,392K,1/16W,1%,THKFLM,0402; CLASS: DISCRETE; DPN: RG205; Lead Free: Yes; Lifecycle Phase: A Revision; Manufacturer: KOA; Manufacturer PN: RK73H1ET-3923F; Material: Thick Film; Package Height: 16 MIL; Package Size: 0402; Package Type: SMD; Part Number: RG205; ROOM: NCSI_ISO; Rated Power: 62.5mW; Rev: A00-00; Tolerance: 1%
R117-R120 R904-R907 = res: RES,100K,1/16W,5%,THKFLM,0402; CLASS: DISCRETE; DPN: 92259; Lead Free: Yes; Lifecycle Phase: A Revision; Manufacturer: KOA; Manufacturer PN: RK73B1ETTP104J; Material: Thick Film; Package Height: 16 MIL; Package Size: 0402; Package Type: SMD; Part Number: 92259; ROOM: NCSI_ISO_TX; Rated Power: 62.5mW; Rev: A00-00; Tolerance: 5%
R121-R124 R908-R911 = res: RES,100K,1/16W,5%,THKFLM,0402; CLASS: DISCRETE; DPN: 92259; Lead Free: Yes; Lifecycle Phase: A Revision; Manufacturer: KOA; Manufacturer PN: RK73B1ETTP104J; Material: Thick Film; Package Height: 16 MIL; Package Size: 0402; Package Type: SMD; Part Number: 92259; ROOM: NCSI_ISO_RX; Rated Power: 62.5mW; Rev: A00-00; Tolerance: 5%
R989 R994 = res: RES,0,1/16W,5%,THKFLM,0402; ALT_SYMBOLS: (SMX0402B); CLASS: DISCRETE; DPN: 92259; Lead Free: Yes; Lifecycle Phase: A Revision; Manufacturer: KOA; Manufacturer PN: RK73Z1ETTP; Material: Thick Film; Package Height: 0.5334 MM; Package Size: 0402; Package Type: SMD; Part Number: N5219; ROOM: NCSI_ISO_TX; Rated Power: 62.5mW; Rev: A00-00; Tolerance: 5%
TP3-TP14 = g_tp: TEST POINT 24; BOM_IGNORE: TRUE; CLASS: DISCRETE; DPN: 00000; Lead Free: N/A; Lifecycle Phase: N/A; Package Height: 1 MIL; Package Type: SMD; Part Number: 160517145612; Rev: N/A
U9 U70 = ltc6994: IC,DELAY,TSOT23-6; CLASS: IC; DPN: DWV66; Lead Free: Yes; Lifecycle Phase: X Revision; Manufacturer: LINEAR TECHNOLOGY; Package Height: 1 MM; Package Size: TSOT23-6; Package Type: SMD; Part Number: DWV66; Rev: X00-00
U10 U69 = sn74auc1g125: IC,AUC1G125,SC70,BUS-BUF-GATE; ALT_SYMBOLS: (SOT65P210X110_5L); CLASS: IC; DPN: GDHXG; Lead Free: Yes; Lifecycle Phase: X Revision; Manufacturer: TEXAS INSTRUMENTS; Manufacturer PN: SN74AUC1G125DCKR; Package Height: 1.1 MM; Package Size: SC70; Package Type: SMD; Part Number: GDHXG; Rev: X00-00
U11 U71 = sn74cbt3126dbq: IC,LV3126,SSOP16,BUS SWT; CLASS: IC; DPN: 1RF08; Lead Free: Yes; Lifecycle Phase: A Revision; Manufacturer: PERICOM SEMICONDUCTOR; Manufacturer PN: PI3B3126QE; Package Height: 1.75 MM; Package Size: SSOP16; Package Type: SMD; Part Number: 1RF08; ROOM: NCSI_ISO_TX; Rev: A00-00
U12 U72 = sn74cbt3126dbq: IC,LV3126,SSOP16,BUS SWT; CLASS: IC; DPN: 1RF08; Lead Free: Yes; Lifecycle Phase: A Revision; Manufacturer: PERICOM SEMICONDUCTOR; Manufacturer PN: PI3B3126QE; Package Height: 1.75 MM; Package Size: SSOP16; Package Type: SMD; Part Number: 1RF08; ROOM: NCSI_ISO_RX; Rev: A00-00
U82 U83 = g_and_1slot_b1_a2: IC,74VHC1G08,SOT353-5,AND; Manufacturer: NXP SEMICONDUCTOR; Package Height: 1.1 MM; Part Number: X6663
C57 C59 C61 C66 C67 C69 C70 C139 C146 = cap: CAP,.1UF,10%,16V,X7R,0402; DEVICE: 090729120334; Part Number: P8155; ROOM: NCSI; TOLERANCE: 10%; VOLTAGE: 16V
C58 C60 = cap: CAP,.1UF,10%,16V,X7R,0402; DEVICE: 090729120334; Part Number: P8155; ROOM: CK_NCSI; TOLERANCE: 10%; VOLTAGE: 16V
C62-C65 C68 C71 C72 = cap: CAP,10UF,20%,6.3V,X5R,0603; DEVICE: 090729120437; Part Number: YT654; ROOM: NCSI; TOLERANCE: 20%; VOLTAGE: 6.3V
C73 C74 = cap: CAP,33PF,10%,50V,C0G,0402; DEVICE: 090729120319; Part Number: P2286; ROOM: NCSI; TOLERANCE: 10%; VOLTAGE: 50V
D5 D6 = g_diode_bi_tvs: DIODE,SRG SUP,24V,SM,0603; DEVICE: 091006150800; Part Number: G9464; TAG1: SRG SUP; TAG2: 24V, 0603
DS1 DS2 = g_led_a1_c2: LED,0603,CLR,GRN,2V,20MA,35MC; DEVICE: 090730110341; Part Number: UJ387; ROOM: NCSI; TAG1: LED, GRN; TAG2: LTST-C191KGKT
J_NCSI = c12raf_rj45magth_2ltp_td: CON,RJ45/MAG,8,R,G,TH,10/1000; DEVICE: 100210192200; Part Number: YR220; ROOM: NCSI; TAG1: RJ45 MAGNETIC JACK W/2 LIGHT PIPES
P_OCP_USB1 = g_c5raf_musb_p8sm_4sh_2peg: CON,USB,5P,F,RH,G,SM,MINI; DEVICE: 100901191600; Part Number: C32TF; TAG1: USB, RT ANGLE; TAG2: SM, MINI-B
R68 = res: RES,33,1/16W,5%,THKFLM,0402; DEVICE: 090729120909; Part Number: J5752; ROOM: ETH; Rated Power: 62.5mW; TOLERANCE: 5%
R69 = res: RES,2.2K,1/16W,5%,THKFLM,0402; DEVICE: 090729120545; Part Number: 6R538; ROOM: CK_NCSI; Rated Power: 62.5mW; TOLERANCE: 5%
R70 R72 R73 = res: RES,33,1/16W,5%,THKFLM,0402; DEVICE: 090729120909; Part Number: J5752; ROOM: NCSI; Rated Power: 62.5mW; TOLERANCE: 5%
R71 R81 R82 = res: RES,2.2K,1/16W,5%,THKFLM,0402; DEVICE: 090729120545; Part Number: 6R538; ROOM: NCSI; Rated Power: 62.5mW; TOLERANCE: 5%
R74 R75 R78 R87 R88 = res: RES,4.7K,1/16W,5%,THKFLM,0402; DEVICE: 090729121131; Part Number: N5300; ROOM: NCSI; Rated Power: 62.5mW; TOLERANCE: 5%
R76 = res: RES,33,1/16W,5%,THKFLM,0402; DEVICE: 090729120909; Part Number: J5752; ROOM: CK_NCSI; Rated Power: 62.5mW; TOLERANCE: 5%
R77 = res: RES,33,1/16W,5%,THKFLM,0402; DEVICE: 090729120909; Part Number: J5752; ROOM: NCSI; Rated Power: 62.5mW; SUB: NP; TOLERANCE: 5%
R79 = res: RES,169,1/16W,1%,THLFLM,0402; DEVICE: 090729120638; Part Number: D7907; ROOM: NCSI; Rated Power: 62.5mW; TOLERANCE: 1%
R80 = res: RES,4.7K,1/16W,1%,THKFLM,0402; DEVICE: 131002134412; Part Number: 3P3J5; ROOM: NCSI; Rated Power: 62.5mW; TOLERANCE: 1%
R83-R86 = res: RES,49.9,1/8W,1%,THKFLM,0805; DEVICE: 090729121112; Part Number: MN371; ROOM: NCSI; Rated Power: 125mW; TOLERANCE: 1%
R89 R90 = res: RES,130,1/16W,1%,THKFLM,0402; DEVICE: 090729120920; Part Number: J8387; ROOM: NCSI; Rated Power: 62.5mW; TOLERANCE: 1%
R988 R993 = res: RES,0,1/16W,5%,THKFLM,0402; ALT_SYMBOLS: (SMX0402B); DEVICE: 090729121131; Manufacturer: KOA; Manufacturer PN: RK73Z1ETTP; Package Height: 0.5334 MM; Part Number: N5219; ROOM: NCSI; Rated Power: 62.5mW; TOLERANCE: 5%
TP1 TP2 = g_tp: TEST POINT 25MIL SQ; DEVICE: 121210082104; Part Number: 00000
U5 = g_osc_4p: OSC,50.00M,50,CT,45,5,SM,3.3V; DEVICE: 091210102800; Part Number: GF009; ROOM: CK_NCSI; TAG1: 50MHz; TAG2: 3.3V
U6 = nc7nz34: IC,NC7NZ34,US8,TRIPLE-BUFFER; DEVICE: 140212135112; Part Number: 4KRH4; ROOM: CK_NCSI; TAG1: NC7NZ34K8X
U86 U87 = pi3usb102-10_0: IC,PI3USB102,TQFN10,USB2.0-MUX; Manufacturer: PERICOM SEMICONDUCTOR; Package Height: 0.8 MM; Part Number: GVY50
U_PHY = dp83848i: IC,DP83848I,ENET TRANSCEIVER,48LQFP; DEVICE: 091203092604; Part Number: VDGXX; ROOM: NCSI; TAG1: DP83848I; TAG2: 48LQFP
C105-C109 C114 C115 C117 C118 = cap: CAP,.1UF,10%,16V,X7R,0402; DEVICE: 090729120334; Part Number: P8155; ROOM: NCSI1; TOLERANCE: 10%; VOLTAGE: 16V
C110-C113 C116 C119 C120 = cap: CAP,10UF,20%,6.3V,X5R,0603; DEVICE: 090729120437; Part Number: YT654; ROOM: NCSI1; TOLERANCE: 20%; VOLTAGE: 6.3V
C121 C122 = cap: CAP,33PF,10%,50V,C0G,0402; DEVICE: 090729120319; Part Number: P2286; ROOM: NCSI1; TOLERANCE: 10%; VOLTAGE: 50V
D11 D12 = g_diode_bi_tvs: DIODE,SRG SUP,24V,SM,0603; DEVICE: 091006150800; Part Number: G9464; ROOM: NCSI1; TAG1: SRG SUP; TAG2: 24V, 0603
DS3 DS4 = g_led_a1_c2: LED,0603,CLR,GRN,2V,20MA,35MC; DEVICE: 090730110341; Part Number: UJ387; ROOM: NCSI1; TAG1: LED, GRN; TAG2: LTST-C191KGKT
J_NCSI_OCP2 = c12raf_rj45magth_2ltp_td: CON,RJ45/MAG,8,R,G,TH,10/1000; DEVICE: 100210192200; Part Number: YR220; ROOM: NCSI1; TAG1: RJ45 MAGNETIC JACK W/2 LIGHT PIPES
P_OCP_USB4 = g_c5raf_musb_p8sm_4sh_2peg: CON,USB,5P,F,RH,G,SM,MINI; DEVICE: 100901191600; Part Number: C32TF; ROOM: NCSI1; TAG1: USB, RT ANGLE; TAG2: SM, MINI-B
R912 R914 R915 R917 R920 = res: RES,33,1/16W,5%,THKFLM,0402; DEVICE: 090729120909; Part Number: J5752; ROOM: NCSI1; Rated Power: 62.5mW; TOLERANCE: 5%
R913 R916 R925 R926 = res: RES,2.2K,1/16W,5%,THKFLM,0402; DEVICE: 090729120545; Part Number: 6R538; ROOM: NCSI1; Rated Power: 62.5mW; TOLERANCE: 5%
R918 R919 R922 R931 R932 = res: RES,4.7K,1/16W,5%,THKFLM,0402; DEVICE: 090729121131; Part Number: N5300; ROOM: NCSI1; Rated Power: 62.5mW; TOLERANCE: 5%
R921 = res: RES,33,1/16W,5%,THKFLM,0402; DEVICE: 090729120909; Part Number: J5752; ROOM: NCSI1; Rated Power: 62.5mW; SUB: NP; TOLERANCE: 5%
R923 = res: RES,169,1/16W,1%,THLFLM,0402; DEVICE: 090729120638; Part Number: D7907; ROOM: NCSI1; Rated Power: 62.5mW; TOLERANCE: 1%
R924 = res: RES,4.7K,1/16W,1%,THKFLM,0402; DEVICE: 131002134412; Part Number: 3P3J5; ROOM: NCSI1; Rated Power: 62.5mW; TOLERANCE: 1%
R927-R930 = res: RES,49.9,1/8W,1%,THKFLM,0805; DEVICE: 090729121112; Part Number: MN371; ROOM: NCSI1; Rated Power: 125mW; TOLERANCE: 1%
R933 R934 = res: RES,130,1/16W,1%,THKFLM,0402; DEVICE: 090729120920; Part Number: J8387; ROOM: NCSI1; Rated Power: 62.5mW; TOLERANCE: 1%
TP15 TP16 = g_tp: TEST POINT 25MIL SQ; DEVICE: 121210082104; Part Number: 00000; ROOM: NCSI1
U73 = g_osc_4p: OSC,50.00M,50,CT,45,5,SM,3.3V; DEVICE: 091210102800; Part Number: GF009; ROOM: NCSI1; TAG1: 50MHz; TAG2: 3.3V
U74 = nc7nz34: IC,NC7NZ34,US8,TRIPLE-BUFFER; DEVICE: 140212135112; Part Number: 4KRH4; ROOM: NCSI1; TAG1: NC7NZ34K8X
U_PHY1 = dp83848i: IC,DP83848I,ENET TRANSCEIVER,48LQFP; DEVICE: 091203092604; Part Number: VDGXX; ROOM: NCSI1; TAG1: DP83848I; TAG2: 48LQFP
C18 C19 C22-C24 C26 C79 C80 C83-C85 C87 C124 C125 C134 = cap: CAP,.1UF,10%,16V,X7R,0402; DEVICE: 090729120334; Part Number: P8155; ROOM: CKBUF; TOLERANCE: 10%; VOLTAGE: 16V
C20 C21 C81 C82 C136 C144 = cap: CAP,10UF,20%,6.3V,X5R,0603; DEVICE: 090729120437; Part Number: YT654; ROOM: CKBUF; TOLERANCE: 20%; VOLTAGE: 6.3V
C25 C86 C126-C128 C145 = cap: CAP,1UF,10%,16V,X7R,0603; DEVICE: 090729120352; Part Number: RY497; TOLERANCE: 10%; VOLTAGE: 16V
C32 = cap_p: cap,220u,20%,6.3V,APOLY; DEVICE: 101104131600; Part Number: XYNR1; ROOM: 3P3VR; TOLERANCE: 20%; VOLTAGE: 6.3V
C33 C34 = cap: CAP,10UF,20%,6.3V,X5R,0603; DEVICE: 090729120437; Part Number: YT654; ROOM: PCIE1; TOLERANCE: 20%; VOLTAGE: 6.3V
C35-C37 C41 = cap: CAP,.1UF,10%,16V,X7R,0402; DEVICE: 090729120334; Part Number: P8155; ROOM: PCIE1; TOLERANCE: 10%; VOLTAGE: 16V
C38 = cap_p: cap,180u,20%,16V,APOLY; DEVICE: 101104132200; Part Number: FFJXY; ROOM: 3P3VR; TOLERANCE: 20%; VOLTAGE: 16V
C39 C40 = cap: CAP,10UF,10%,16V,X7R,1206; DEVICE: 090729120355; Part Number: TK479; ROOM: PCIE1; TOLERANCE: 10%; VOLTAGE: 16V
DS_3P3AUX DS_12V = g_led_a1_c2: LED,0603,CLR,GRN,2.5V,2MA,SMD; CLASS: DISCRETE; DPN: P0HK6; LED Color: GRN; Lead Free: Yes; Lifecycle Phase: X Revision; Manufacturer: KINGBRIGHT CORPORATION; Package Height: 0.95 MM; Package Size: 0603; Package Type: SMD; Part Number: P0HK6; Rev: X00-00; Voltage: 2.5V
F1 = fuse: FUSE,20A,32V,HOLDER,FORK,TH; CLASS: DISCRETE; DPN: 1HD9C; Lead Free: Yes; Lifecycle Phase: Preliminary; Manufacturer: LITTELFUSE; Manufacturer PN: 01530008Z; Package Height: 12.9 MM; Package Type: TH; Part Number: 1HD9C; Rev: Introductory
L1 L3 L33 L36 = g_ind: FE,BEAD,200MA,0603,600OHM@100M; DEVICE: 090729180941; Part Number: JW704; Rated Current: 200m
P3 P4 = g_2x4_oe: CON,HDR,2X4,M,.1X.32,S,T,U,TH; CLASS: IO; DPN: XM354; Lead Free: Yes; Lifecycle Phase: A Revision; Manufacturer: FCI; Manufacturer PN: 68691-408HLF; Package Height: 426 MIL; Package Size: HDR2X4; Package Type: TH; Part Number: XM354; Pin Info: 2.54MM PITCH; Rev: A00-00
P_12V P_GND = g_2x5_ss: CON,HSG,2X5,F,S,PWRTAP; Manufacturer: TYCO ELECTRONICS; Manufacturer PN: 5055673-2; Package Height: 375 MIL; Part Number: DJG4H
P_ATX1 = g_2x12_ss_2mh: CON,2X12P,F,ATX PWR,S,TH; CLASS: IO; DPN: JT640; Lead Free: Yes; Lifecycle Phase: Preliminary; Manufacturer: FOXCONN; Manufacturer PN: HM3512E-P2; Package Height: 13.1826 MM; Package Type: TH; Part Number: JT640; Rev: Introductory
R21 R22 R24 R26-R28 R32 R33 R138 R139 R142-R145 R149 R150 = res: RES,0,1/16W,5%,THKFLM,0402; DEVICE: 090729121124; Part Number: N5219; ROOM: CKBUF; Rated Power: 62.5mW; TOLERANCE: 5%
R23 R25 R140 R141 = res: RES,42.2,1/16W,1%,THKFLM,0402; DEVICE: 090729121124; Manufacturer: CYNTEC; Manufacturer PN: PFR05S42R2F; Package Height: 0.5334 MM; Part Number: G861N; ROOM: CKBUF; Rated Power: 62.5mW; TOLERANCE: 1%
R29-R31 R34 R146-R148 R151 R950-R953 R956 R963 R992 = res: RES,1K,1/32W,5%,THKFLM,0402; DEVICE: 091106110100; Part Number: 92260; Rated Power: 31.25mW; TOLERANCE: 5%
R35 R152 R954 R955 R957 R962 R964 R965 = res: RES,1K,1/32W,5%,THKFLM,0402; DEVICE: 091106110100; Part Number: 92260; Rated Power: 31.25mW; SUB: NP; TOLERANCE: 5%
R36 R153 = res: RES,1,1/10W,5%,THKFLM,0603; DEVICE: 090729121545; Part Number: YW788; Rated Power: 100mW; TOLERANCE: 5%
R38 = res: RES,324,1/16W,1%,THKFLM,0402; CLASS: DISCRETE; DPN: D9921; Lead Free: Yes; Lifecycle Phase: A Revision; Manufacturer: KOA; Manufacturer PN: RK73H1ETTP3240F; Package Height: 16 MIL; Package Size: 0402; Package Type: SMD; Part Number: D9921; Rated Power: 62.5mW; Rev: A00-00; Tolerance: 1%
R40 = res: RES,4.7K,1/10W,5%,THKFLM,0603; CLASS: DISCRETE; DPN: J5763; Lead Free: Yes; Lifecycle Phase: A Revision; Manufacturer: SEI ELECTRONICS INC; Manufacturer PN: RMCF 1/16 4.7K 5%; Package Height: 26 MIL; Package Size: 0603; Package Type: SMD; Part Number: J5763; Rated Power: 100mW; Rev: A00-00; Tolerance: 5%
R104 = res: RES,5.1K,1/16W,1%,THKFLM,0402; CLASS: DISCRETE; DPN: X9651; Lead Free: Yes; Lifecycle Phase: A Revision; Manufacturer: SEI ELECTRONICS INC; Manufacturer PN: RMCF 1/16S 5101 1%; Material: Thick Film; Package Height: 16 MIL; Package Size: 0402; Package Type: SMD; Part Number: X9651; Rated Power: 62.5mW; Rev: A00-00; Tolerance: 1%
R105 = res: RES,10K,1/16W,1%,THKFLM,0402; CLASS: DISCRETE; DEVICE: 090729121122; DPN: N1256; Lead Free: Yes; Lifecycle Phase: A Revision; Manufacturer: KOA; Manufacturer PN: RK73H1ETTP1002F; Material: Thick Film; Package Height: 16 MIL; Package Size: 0402; Package Type: SMD; Part Number: N1256; ROOM: BRD1; Rated Power: 62.5mW; Rev: A00-00; TOLERANCE: 1%
R106 = res: RES,100K,1/16W,5%,THKFLM,0402; CLASS: DISCRETE; DPN: 92259; Lead Free: Yes; Lifecycle Phase: A Revision; Manufacturer: KOA; Manufacturer PN: RK73B1ETTP104J; Material: Thick Film; Package Height: 16 MIL; Package Size: 0402; Package Type: SMD; Part Number: 92259; Rated Power: 62.5mW; Rev: A00-00; Tolerance: 5%
R156-R163 = res: RES,1K,1/32W,5%,THKFLM,0402; CLASS: DISCRETE; DEVICE: 090729121124; DPN: 92260; Lead Free: ESG-X; Lifecycle Phase: A Revision; Manufacturer: KOA; Manufacturer PN: RK73B1ETTP102J; Material: Thick Film; Package Height: 16 MIL; Package Size: 0402; Package Type: SMD; Part Number: 92260; ROOM: CKBUF; Rated Power: 31.25mW; Rev: A00-00; TOLERANCE: 5%
R984-R987 = res: RES,88.7,1/16W,1%,THKFLM,0402; DEVICE: 091106110100; Manufacturer: SEI ELECTRONICS INC; Manufacturer PN: RMCF 1/16S 88.7 1%; Package Height: 0.5334 MM; Part Number: 98FVG; Rated Power: 62.5mW; TOLERANCE: 1%
SW_PWR1 = g_2x3_ss: SWT,SL,DPDT,0.2A@30VDC; CLASS: DISCRETE; DPN: 0C94G; Lead Free: Yes; Lifecycle Phase: X Revision; Manufacturer: E-SWITCH; Manufacturer PN: EG2207; Package Height: 7.9 MM; Package Type: TH; Part Number: 0C94G; ROOM: BRD1; Rev: X00-00
U4 U13 = 9dbl04: IC,BUFFER,VFQFPN32,4-OUTPUT; DEVICE: 160331090612; Part Number: 160331090612; SUB: SUB*_R48TD; TAG1: 9DBL0452BKILFT; TAG2: VFQFPN32
U8 = max811: IC,811,SOT143,2.63V; CLASS: IC; DPN: 2E549; Lead Free: No; Lifecycle Phase: A Revision; Manufacturer: IMP; Manufacturer PN: IMP811REUS-T; Package Height: 1.22 MM; Package Size: SOT143; Package Type: SMD; Part Number: 2E549; Rev: A00-00; Voltage: 2.63V
U75 = g_or_1slot_a1_b2: IC,74LVC1G32,SOT23-5,OR; Manufacturer: NXP SEMICONDUCTOR; Package Height: 1.45 MM; Part Number: DX055
U77 U78 = SI53307-B-GM: IC,SI53307-B,QFN16,2OUT,CLKBUF; Manufacturer: SILICON LABORATORIES; Package Height: 0.9 MM; Part Number: GYG4F
U81 = g_1slot_nc1_a2: IC,74LVC1G07,TSSOP5,BUFFER; Manufacturer: NXP SEMICONDUCTOR; Package Height: 1.1 MM; Part Number: MMDRC

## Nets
12V_OK: U75.1(A) ; also on sheet 15
GND: C18.1 C19.1 C20.1 C21.1 C22.1 C23.1 C24.1 C25.2 C26.1 C32.2 C33.1 C34.1 C35.1 C36.1 C37.1 C38.2 C39.1 C40.1 C41.1 C57.2 C58.1 C59.2 C60.1 C61.1 C62.1 C63.1 C64.1 C65.1 C66.1 C67.1 C68.1 C69.1 C70.1 C71.1 C72.1 C73.1 C74.1 C75.1 C76.1 C77.1 C78.1 C79.1 C80.1 C81.1 C82.1 C83.1 C84.1 C85.1 C86.2 C87.1 C101.1 C102.1 C103.1 C104.1 C105.2 C106.1 C107.2 C108.1 C109.1 C110.1 C111.1 C112.1 C113.1 C114.1 C115.1 C116.1 C117.1 C118.1 C119.1 C120.1 C121.1 C122.1 C124.1 C125.1 C126.2 C127.2 C128.2 C134.1 C136.1 C137.1 C138.1 C139.1 C144.1 C145.2 C146.1 D5.1(2) D6.1(2) D11.1(2) D12.1(2) DS_3P3AUX.2(C) DS_12V.2(C) J_NCSI.SH1 J_NCSI.SH2 J_NCSI_OCP2.SH1 J_NCSI_OCP2.SH2 P9.3 P10.3 P_ATX1.3 P_ATX1.5 P_ATX1.7 P_ATX1.15 P_ATX1.17 P_ATX1.18 P_ATX1.19 P_ATX1.24 P_GND.1 P_GND.2 P_GND.3 P_GND.4 P_GND.5 P_GND.6 P_GND.7 P_GND.8 P_GND.9 P_GND.10 P_OCP_USB1.5 P_OCP_USB1.SH1 P_OCP_USB1.SH2 P_OCP_USB1.SH3 P_OCP_USB1.SH4 P_OCP_USB4.5 P_OCP_USB4.SH1 P_OCP_USB4.SH2 P_OCP_USB4.SH3 P_OCP_USB4.SH4 R29.1 R30.1 R31.1 R35.1 R74.1 R75.1 R78.2 R79.1 R105.1 R106.1 R115.1 R116.1 R117.2 R118.2 R119.2 R120.1 R121.2 R122.2 R123.2 R124.1 R146.1 R147.1 R148.1 R152.1 R902.1 R903.1 R904.2 R905.2 R906.2 R907.1 R908.2 R909.2 R910.2 R911.1 R918.1 R919.1 R922.2 R923.1 R950.1 R951.1 R955.1 R957.1 R964.1 R965.1 R984.1 R985.1 R986.1 R987.1 R988.1 R993.1 SW_PWR1.6 U4.8(GNDDIG) U4.33(EPAD) U5.2(GND) U6.4(GND) U8.1(GND) U9.2(GND) U10.1(OE_N) U10.3(GND) U11.8(GND) U12.8(GND) U13.8(GNDDIG) U13.33(EPAD) U69.1(OE_N) U69.3(GND) U70.2(GND) U71.8(GND) U72.8(GND) U73.2(GND) U74.4(GND) U75.3(GND) U77.4(GND1) U77.15(GND2) U77.17(GND_PAD) U78.4(GND1) U78.15(GND2) U78.17(GND_PAD) U81.3(GND) U82.3(GND) U83.3(GND) U86.3(GND) U87.3(GND) U_PHY.15(AGND) U_PHY.19(AGND) U_PHY.35(IOGND) U_PHY.36(DGND) U_PHY.47(IOGND) U_PHY1.15(AGND) U_PHY1.19(AGND) U_PHY1.35(IOGND) U_PHY1.36(DGND) U_PHY1.47(IOGND) ; also on sheet 4 5 6 7 8 15 16
ATX_PS_ON_N: P_ATX1.16 SW_PWR1.5
ATX_PWR_OK: P_ATX1.8 U75.2(B) ; also on sheet 5
ATX_PWR_OK_33: R104.1 R105.2 U8.3(~{MR})
AUX_EN: R106.2 U8.2(~{RESET}) U9.1(IN) U81.2(A) ; also on sheet 5 6
AUX_EN_OCP2: U70.1(IN) U81.4(Y) ; also on sheet 5 7
CK_50M_MEZZ_R: R68.1 U6.7(1Y)
CK_50M_MEZZ_R_OCP2: R912.1 U74.7(1Y)
CK_50M_NCSI_BUF: U5.3(OUT) U6.1(1A) U6.3(2A) U6.6(3A)
CK_50M_NCSI_OCP2_BUF: U73.3(OUT) U74.1(1A) U74.3(2A) U74.6(3A)
CK_50M_NCSI_OCP2_PHY: R920.2 U_PHY1.34(X1)
CK_50M_NCSI_PHY: R76.2 U_PHY.34(X1)
CK_50M_NCSI_PHY_R: R76.1 U6.2(3Y)
CK_50M_NCSI_PHY_R_OCP2: R920.1 U74.2(3Y)
CK_100M_PE_0_C_DN: R22.2 U4.14(DIF0#)
CK_100M_PE_0_C_DP: R21.2 U4.13(DIF0)
CK_100M_PE_1_C_DN: R26.2 U4.18(DIF1#)
CK_100M_PE_1_C_DP: R24.2 U4.17(DIF1)
CK_100M_PE_2_C_DN: R28.2 U4.23(DIF2#)
CK_100M_PE_2_C_DP: R27.2 U4.22(DIF2)
CK_100M_PE_3_C_DN: R33.2 U4.28(DIF3#)
CK_100M_PE_3_C_DP: R32.2 U4.27(DIF3)
CK_100M_PE_4_C_DN: R139.2 U13.14(DIF0#)
CK_100M_PE_4_C_DP: R138.2 U13.13(DIF0)
CK_100M_PE_5_C_DN: R143.2 U13.18(DIF1#)
CK_100M_PE_5_C_DP: R142.2 U13.17(DIF1)
CK_100M_PE_6_C_DN: R145.2 U13.23(DIF2#)
CK_100M_PE_6_C_DP: R144.2 U13.22(DIF2)
CK_100M_PE_7_C_DN: R150.2 U13.28(DIF3#)
CK_100M_PE_7_C_DP: R149.2 U13.27(DIF3)
CK_100M_PE_EDGE1_C_DN: R140.1 R986.2 U13.6(CLK_IN#)
CK_100M_PE_EDGE1_C_DP: R141.1 R987.2 U13.5(CLK_IN)
CK_100M_PE_EDGE_C_DN: R25.1 R984.2 U4.6(CLK_IN#)
CK_100M_PE_EDGE_C_DP: R23.1 R985.2 U4.5(CLK_IN)
CK_100M_PE_HOST1_DN: U77.7(CLK0b) ; also on sheet 8
CK_100M_PE_HOST1_DP: U77.6(CLK0) ; also on sheet 8
CK_100M_PE_HOST2_DN: U78.3(CLK1b) ; also on sheet 16
CK_100M_PE_HOST2_DP: U78.2(CLK1) ; also on sheet 16
CK_100M_PE_OCP2_DN: U77.9(Q1b) U78.7(CLK0b)
CK_100M_PE_OCP2_DP: U77.10(Q1) U78.6(CLK0)
CLK_100M_OCP0_DN: R22.1 ; also on sheet 6
CLK_100M_OCP0_DP: R21.1 ; also on sheet 6
CLK_100M_OCP1_DN: R26.1 ; also on sheet 6
CLK_100M_OCP1_DP: R24.1 ; also on sheet 6
CLK_100M_OCP2_DN: R28.1 ; also on sheet 6
CLK_100M_OCP2_DP: R27.1 ; also on sheet 6
CLK_100M_OCP3_DN: R33.1 ; also on sheet 6
CLK_100M_OCP3_DP: R32.1 ; also on sheet 6
CLK_100M_OCP4_DN: R139.1 ; also on sheet 7
CLK_100M_OCP4_DP: R138.1 ; also on sheet 7
CLK_100M_OCP5_DN: R143.1 ; also on sheet 7
CLK_100M_OCP5_DP: R142.1 ; also on sheet 7
CLK_100M_OCP6_DN: R145.1 ; also on sheet 7
CLK_100M_OCP6_DP: R144.1 ; also on sheet 7
CLK_100M_OCP7_DN: R150.1 ; also on sheet 7
CLK_100M_OCP7_DP: R149.1 ; also on sheet 7
CLK_NCSI: R68.2 ; also on sheet 6
CLK_NCSI_OCP2: R912.2 ; also on sheet 7
MDI_NCSI_RX_DN: J_NCSI.5(TRD2-) R86.1 U_PHY.13(RD-)
MDI_NCSI_RX_DP: J_NCSI.4(TRD2+) R85.1 U_PHY.14(RD+)
MDI_NCSI_RX_OCP2_DN: J_NCSI_OCP2.5(TRD2-) R930.1 U_PHY1.13(RD-)
MDI_NCSI_RX_OCP2_DP: J_NCSI_OCP2.4(TRD2+) R929.1 U_PHY1.14(RD+)
MDI_NCSI_TX_DN: J_NCSI.10(TRD1-) R84.1 U_PHY.16(TD-)
MDI_NCSI_TX_DP: J_NCSI.11(TRD1+) R83.1 U_PHY.17(TD+)
MDI_NCSI_TX_OCP2_DN: J_NCSI_OCP2.10(TRD1-) R928.1 U_PHY1.16(TD-)
MDI_NCSI_TX_OCP2_DP: J_NCSI_OCP2.11(TRD1+) R927.1 U_PHY1.17(TD+)
NC_NCSI_PHY_PWR_DOWN: U_PHY.7(PWR_DOWN/INT)
NC_NCSI_PHY_PWR_DOWN_OCP2: U_PHY1.7(PWR_DOWN/INT)
NCSI_ACT_N: DS1.2(C) R88.1 U_PHY.26(LED_ACT/COL/AN_EN)
NCSI_ACT_OCP2_N: DS3.2(C) R932.1 U_PHY1.26(LED_ACT/COL/AN_EN)
NCSI_CRSDV_R: R77.1 U_PHY.40(CRS/CRS_DV/LED_CFG)
NCSI_CRSDV_R_OCP2: R921.1 U_PHY1.40(CRS/CRS_DV/LED_CFG)
NCSI_LINK_N: DS2.2(C) R87.1 U_PHY.28(LED_LINK/AN0)
NCSI_LINK_OCP2_N: DS4.2(C) R931.1 U_PHY1.28(LED_LINK/AN0)
NCSI_PHY_PF: C62.2 C63.2 C64.2 C65.2 U_PHY.18(PFBIN1) U_PHY.23(PFBOUT) U_PHY.37(PFBIN2)
NCSI_PHY_PF_OCP2: C110.2 C111.2 C112.2 C113.2 U_PHY1.18(PFBIN1) U_PHY1.23(PFBOUT) U_PHY1.37(PFBIN2)
NCSI_RST_N: U_PHY.29(RESET_N) ; also on sheet 5
NCSI_RST_OCP2_N: U_PHY1.29(RESET_N) ; also on sheet 5
NCSI_RXD0_R: R73.1 U_PHY.43(RXD_0/PHYAD1)
NCSI_RXD0_R_OCP2: R914.1 U_PHY1.43(RXD_0/PHYAD1)
NCSI_RXD1_R: R70.1 U_PHY.44(RXD_1/PHYAD2)
NCSI_RXD1_R_OCP2: R915.1 U_PHY1.44(RXD_1/PHYAD2)
NCSI_RXDV_R: R71.1 R72.1 U_PHY.39(RX_DV/MII_MODE)
NCSI_RXDV_R_OCP2: R916.1 R917.1 U_PHY1.39(RX_DV/MII_MODE)
NIC_PWR_GOOD_OCP1: U82.2(A) ; also on sheet 5 6
NIC_PWR_GOOD_OCP2: U83.2(A) ; also on sheet 5 7
OCP2_CLK_SEL: U78.14(CLK_SEL) ; also on sheet 5
OCP_NCSI_CRS_DV: U12.10(B2) ; also on sheet 6
OCP_NCSI_CRS_DV_OCP2: U72.10(B2) ; also on sheet 7
OCP_NCSI_CRS_DV_OCP2_PHY: R911.2 TP14.TEST U72.11(A2) U_PHY1.2(TX_EN)
OCP_NCSI_CRS_DV_PHY: R124.2 TP8.TEST U12.11(A2) U_PHY.2(TX_EN)
OCP_NCSI_RXD0: U12.4(B0) ; also on sheet 6
OCP_NCSI_RXD0_OCP2: U72.4(B0) ; also on sheet 7
OCP_NCSI_RXD0_OCP2_PHY: R908.1 TP12.TEST U72.3(A0) U_PHY1.3(TXD_0)
OCP_NCSI_RXD0_PHY: R121.1 TP6.TEST U12.3(A0) U_PHY.3(TXD_0)
OCP_NCSI_RXD1: U12.7(B1) ; also on sheet 6
OCP_NCSI_RXD1_OCP2: U72.7(B1) ; also on sheet 7
OCP_NCSI_RXD1_OCP2_PHY: R909.1 TP13.TEST U72.6(A1) U_PHY1.4(TXD_1)
OCP_NCSI_RXD1_PHY: R122.1 TP7.TEST U12.6(A1) U_PHY.4(TXD_1)
OCP_NCSI_TXD0: U11.4(B0) ; also on sheet 6
OCP_NCSI_TXD0_OCP2: U71.4(B0) ; also on sheet 7
OCP_NCSI_TXD0_OCP2_PHY: R904.1 R914.2 TP9.TEST U71.3(A0)
OCP_NCSI_TXD0_PHY: R73.2 R117.1 TP3.TEST U11.3(A0)
OCP_NCSI_TXD1: U11.7(B1) ; also on sheet 6
OCP_NCSI_TXD1_OCP2: U71.7(B1) ; also on sheet 7
OCP_NCSI_TXD1_OCP2_PHY: R905.1 R915.2 TP10.TEST U71.6(A1)
OCP_NCSI_TXD1_PHY: R70.2 R118.1 TP4.TEST U11.6(A1)
OCP_NCSI_TXEN: U11.10(B2) ; also on sheet 6
OCP_NCSI_TXEN_OCP2: U71.10(B2) ; also on sheet 7
OCP_NCSI_TXEN_OCP2_PHY: R907.2 R917.2 R921.2 TP11.TEST U71.11(A2)
OCP_NCSI_TXEN_PHY: R72.2 R77.2 R120.2 TP5.TEST U11.11(A2)
PLL_BW: R34.1 R35.2 U4.1(^VHIBW_BYPM_LOB)
PLL_BW1: R151.1 R152.2 U13.1(^VHIBW_BYPM_LOB)
RBT_ISOLATE_EN: P9.2 R989.1 U11.2(BE0) U11.5(BE1) U11.12(BE2) U11.15(BE3) U12.2(BE0) U12.5(BE1) U12.12(BE2) U12.15(BE3) U86.10(SEL)
RBT_ISOLATE_EN_OCP2: P10.2 R994.1 U71.2(BE0) U71.5(BE1) U71.12(BE2) U71.15(BE3) U72.2(BE0) U72.5(BE1) U72.12(BE2) U72.15(BE3) U87.10(SEL)
SFOUT0_U77: R954.1 R955.2 U77.13(SFOUT0)
SFOUT0_U78: R962.1 R964.2 U78.13(SFOUT0)
SFOUT1_U77: R956.1 R957.2 U77.8(SFOUT1)
SFOUT1_U78: R963.1 R965.2 U78.8(SFOUT1)
TP_NCSI_MDC: TP1.TEST U_PHY.31(MDC)
TP_NCSI_MDC_OCP2: TP15.TEST U_PHY1.31(MDC)
TP_NCSI_MDIO: TP2.TEST U_PHY.30(MDIO)
TP_NCSI_MDIO_OCP2: TP16.TEST U_PHY1.30(MDIO)
USB_DAT_OCP2_DN: U87.2(Y-) ; also on sheet 7
USB_DAT_OCP2_DP: U87.1(Y+) ; also on sheet 7
USB_DATN: U86.2(Y-) ; also on sheet 6
USB_DATP: U86.1(Y+) ; also on sheet 6
V_3P3AUX: C32.1 C33.2 C34.2 C35.2 C36.2 C57.1 C58.2 C59.1 C60.2 C61.2 C66.2 C67.2 C68.2 C69.2 C70.2 C71.2 C72.2 C73.2 C74.2 C75.2 C76.2 C77.2 C78.2 C101.2 C102.2 C103.2 C104.2 C105.1 C106.2 C107.1 C108.2 C109.2 C114.2 C115.2 C116.2 C117.2 C118.2 C119.2 C120.2 C121.2 C122.2 C124.2 C125.2 C126.1 C128.1 C134.2 C137.2 C138.2 C139.2 C146.2 J_NCSI.6(TRCT2) J_NCSI.12(TRCT1) J_NCSI_OCP2.6(TRCT2) J_NCSI_OCP2.12(TRCT1) L1.1 L3.1 L33.1 L36.1 P3.2 P3.4 P3.6 P3.8 P4.2 P4.4 P4.6 P4.8 P9.1 P10.1 R34.2 R38.2 R69.1 R71.2 R81.1 R82.1 R83.2 R84.2 R85.2 R86.2 R87.2 R88.2 R89.1 R90.1 R114.2 R151.2 R901.2 R913.1 R916.2 R925.1 R926.1 R927.2 R928.2 R929.2 R930.2 R931.2 R932.2 R933.1 R934.1 R952.2 R954.2 R956.2 R962.2 R963.2 U5.4(VCC) U6.8(VCC) U8.4(VCC) U9.5(V+) U10.5(VCC) U11.16(VCC) U12.16(VCC) U69.5(VCC) U70.5(V+) U71.16(VCC) U72.16(VCC) U73.4(VCC) U74.8(VCC) U75.5(VCC) U77.1(VDD) U78.1(VDD) U81.5(VCC) U82.5(VCC) U83.5(VCC) U86.9(VDD) U87.9(VDD) U_PHY.22(AVDD33) U_PHY.32(IOVDD33) U_PHY.48(IOVDD33) U_PHY1.22(AVDD33) U_PHY1.32(IOVDD33) U_PHY1.48(IOVDD33) ; also on sheet 4 5 6 7 8 15 16
V_5VSTBY_FUSE: P_ATX1.9
V_12V: C37.2 C38.1 C39.2 C40.2 C41.2 F1.2 R40.2 ; also on sheet 4 6 7 15
V_12V_FUSE: F1.1 P_12V.1 P_12V.2 P_12V.3 P_12V.4 P_12V.5 P_12V.6 P_12V.7 P_12V.8 P_12V.9 P_12V.10 P_ATX1.10 P_ATX1.11
V_VDD_CLK: C18.2 C19.2 C20.2 C21.2 C22.2 C23.2 C24.2 L1.2 R36.1 U4.11(VDDDIG3.3) U4.15(VDDO3.3) U4.25(VDDO3.3)
V_VDD_CLK1: C79.2 C80.2 C81.2 C82.2 C83.2 C84.2 C85.2 L3.2 R153.1 U13.11(VDDDIG3.3) U13.15(VDDO3.3) U13.25(VDDO3.3)
V_VDDA_PLL: C25.1 C26.2 R36.2 U4.4(VDDR3.3) U4.21(VDDA3.3)
V_VDDA_PLL1: C86.1 C87.2 R153.2 U13.4(VDDR3.3) U13.21(VDDA3.3)
N16779825: DS_12V.1(A) R40.1
N16779827: DS_3P3AUX.1(A) R38.1
N16828726: R23.2 U77.12(Q0)
N16828728: R25.2 U77.11(Q0b)
N16828782: R29.2 U4.32(^SADR_TRI)
N16828810: R30.2 U4.10(SDATA_3.3)
N16828818: R31.2 U4.9(SCLK_3.3)
N16918699: DS1.1(A) R89.2
N16918737: DS2.1(A) R90.2
N16919036: R69.2 U5.1(E/D)
N16919082: R74.2 U_PHY.5(TXD_2)
N16919094: R75.2 U_PHY.6(TXD_3/SNI_MODE)
N16919146: R81.2 U_PHY.20(RESERVED1)
N16919148: R82.2 U_PHY.21(RESERVED2)
N16919150: R79.2 R80.1
N16919156: R80.2 U_PHY.24(RBIAS)
N16919307: R78.1 U_PHY.8(TCK)
N16979827: D5.2(1) P_OCP_USB1.2 U86.6(D-)
N16979834: D6.2(1) P_OCP_USB1.3 U86.7(D+)
N17011624: R104.2 U75.4(Y)
N17019313: R114.1 R116.2 U9.4(DIV)
N17019331: R989.2 U10.4(Y)
N17019354: R115.2 U9.3(SET)
N17019798: R119.1 U11.14(A3)
N17020060: R123.1 U12.14(A3)
N17051716: R146.2 U13.32(^SADR_TRI)
N17051768: R147.2 U13.10(SDATA_3.3)
N17051781: R148.2 U13.9(SCLK_3.3)
N17102204: P3.7 R156.2
N17102209: P3.5 R157.2
N17102219: P3.3 R158.2
N17102224: P3.1 R159.2
N17102733: R156.1 U4.12(VOE0#)
N17102736: R157.1 U4.19(VOE1#)
N17102739: R158.1 U4.24(VOE2#)
N17102742: R159.1 U4.29(VOE3#)
N17102933: P4.1 R163.2
N17102935: P4.3 R162.2
N17102937: P4.5 R161.2
N17102939: P4.7 R160.2
N17102969: R161.1 U13.19(VOE1#)
N17102999: R163.1 U13.29(VOE3#)
N17103110: R160.1 U13.12(VOE0#)
N17103113: R162.1 U13.24(VOE2#)
N17201699: R901.1 R903.2 U70.4(DIV)
N17201720: R902.2 U70.3(SET)
N17201970: R906.1 U71.14(A3)
N17202190: R910.1 U72.14(A3)
N17204111: R913.2 U73.1(E/D)
N17204373: R918.2 U_PHY1.5(TXD_2)
N17204391: R919.2 U_PHY1.6(TXD_3/SNI_MODE)
N17204565: R922.1 U_PHY1.8(TCK)
N17204599: R923.2 R924.1
N17204601: R924.2 U_PHY1.24(RBIAS)
N17204625: R925.2 U_PHY1.20(RESERVED1)
N17204647: R926.2 U_PHY1.21(RESERVED2)
N17205036: DS3.1(A) R933.2
N17205198: D11.2(1) P_OCP_USB4.2 U87.6(D-)
N17205236: D12.2(1) P_OCP_USB4.3 U87.7(D+)
N17205246: DS4.1(A) R934.2
N17277794: C127.1 C136.2 L33.2 R953.2 U77.5(VDDO)
N17279071: R950.2 U77.14(CLK_SEL)
N17279639: R951.2 U77.3(CLK1b)
N17280125: R952.1 U77.2(CLK1)
N17280888: R953.1 U77.16(OE)
N17282156: R992.1 U78.16(OE)
N17282162: R141.2 U78.12(Q0)
N17282168: R140.2 U78.11(Q0b)
N17370883: U10.2(A) U82.4(Y)
N17370889: U9.6(OUT) U82.1(B)
N17376121: U69.2(A) U83.4(Y)
N17376123: U70.6(OUT) U83.1(B)
N17383263: R988.2 U86.8(OE_N)
N17395273: C144.2 C145.1 L36.2 R992.2 U78.5(VDDO)
N17396869: R993.2 U87.8(OE_N)
N17431570: R994.2 U69.4(Y)

Not connected (* = marked no-connect by the designer): J_NCSI 1(TRCT3) 2(TRD3-) 3(TRD3+) 7(TRCT4) 8(TRD4+) 9(TRD4-); J_NCSI_OCP2 1(TRCT3) 2(TRD3-) 3(TRD3+) 7(TRCT4) 8(TRD4+) 9(TRD4-); P_ATX1 1* 2* 4* 6* 12* 13* 14* 20* 21* 22* 23*; P_OCP_USB1 1* 4; P_OCP_USB4 1* 4; SW_PWR1 1* 2* 3* 4*; U4 2(FB_DNC)* 3(FB_DNC#)* 7(NC)* 16(NC)* 20(NC)* 26(NC)* 30(NC)* 31(^CKPWRGD_PD#)*; U6 5(2Y)*; U11 1(NC)* 9(NC)* 13(B3)*; U12 1(NC)* 9(NC)* 13(B3)*; U13 2(FB_DNC)* 3(FB_DNC#)* 7(NC)* 16(NC)* 20(NC)* 26(NC)* 30(NC)* 31(^CKPWRGD_PD#)*; U71 1(NC)* 9(NC)* 13(B3)*; U72 1(NC)* 9(NC)* 13(B3)*; U74 5(2Y)*; U78 9(Q1b)* 10(Q1)*; U81 1(NC)*; U86 4(M-)* 5(M+)*; U87 4(M-)* 5(M+)*; U_PHY 1(TX_CLK)* 9(TDO)* 10(TMS)* 11(TRST_N)* 12(TDI)* 25(25MHZ_OUT) 27(LED_SPEED/AN1)* 33(X2)* 38(RX_CLK)* 41(RX_ER/MDIX_EN)* 42(COL/PHYAD0)* 45(RXD_2/PHYAD3)* 46(RXD_3/PHYAD4)*; U_PHY1 1(TX_CLK)* 9(TDO)* 10(TMS)* 11(TRST_N)* 12(TDI)* 25(25MHZ_OUT) 27(LED_SPEED/AN1)* 33(X2)* 38(RX_CLK)* 41(RX_ER/MDIX_EN)* 42(COL/PHYAD0)* 45(RXD_2/PHYAD3)* 46(RXD_3/PHYAD4)*

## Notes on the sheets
sheet 10
- REMOVE R989 AND USE SHUNT ON P9 FOR MANUAL RBT ISOLATE CONTROL FOR OCP1 (OCP2:  R994 / P10)
- ROOM=NCSI_ISO
- ROOM = NCSI_ISO_TX
- ROOM = NCSI_ISO_TX
- ROOM = NCSI_ISO_RX
- ROOM = NCSI_ISO_RX
sheet 11
- NCSI Phy, RJMag and USB port
  Primary Connector
- ROOM=CK_NCSI
- P01 BRM
  U_MPHY pin 41 no connect
  NCSI_RXER connection revomed
- ROOM=NCSI
sheet 12
- NCSI Phy, RJMag and USB port
  Secondary Connector
- ROOM=CK_NCSI
- P01 BRM
  U_MPHY pin 41 no connect
  NCSI_RXER connection revomed
- ROOM=NCSI1
sheet 13
- PCIe Clk Buffer Primary Connector
- PLL_BW = high -> PLL Hi BW
  PLL_BW = low  -> PLL Lo BW
- If Spread Modulation is used, Populate R1413. PLL wil be in bypass mode.
- MAX811 Reset Active Timeout Period Trp: 140 - 560ms
- Decoupling Capacitors
- USE EITHER SCREW TERMINALS
  OR ATX POWER
- Power Switch
- 20A FUSE HOLDER
  USE FUSE TYPE:
  LITTLEFUSE 32V AUTO
  MINI BLADE
- ATX Power Connector
sheet 14
- PCIe Clk Buffer Secondary OCP connector
- PLL_BW = high -> PLL Hi BW
  PLL_BW = low  -> PLL Lo BW
- If Spread Modulation is used, Populate R1413. PLL wil be in bypass mode.
